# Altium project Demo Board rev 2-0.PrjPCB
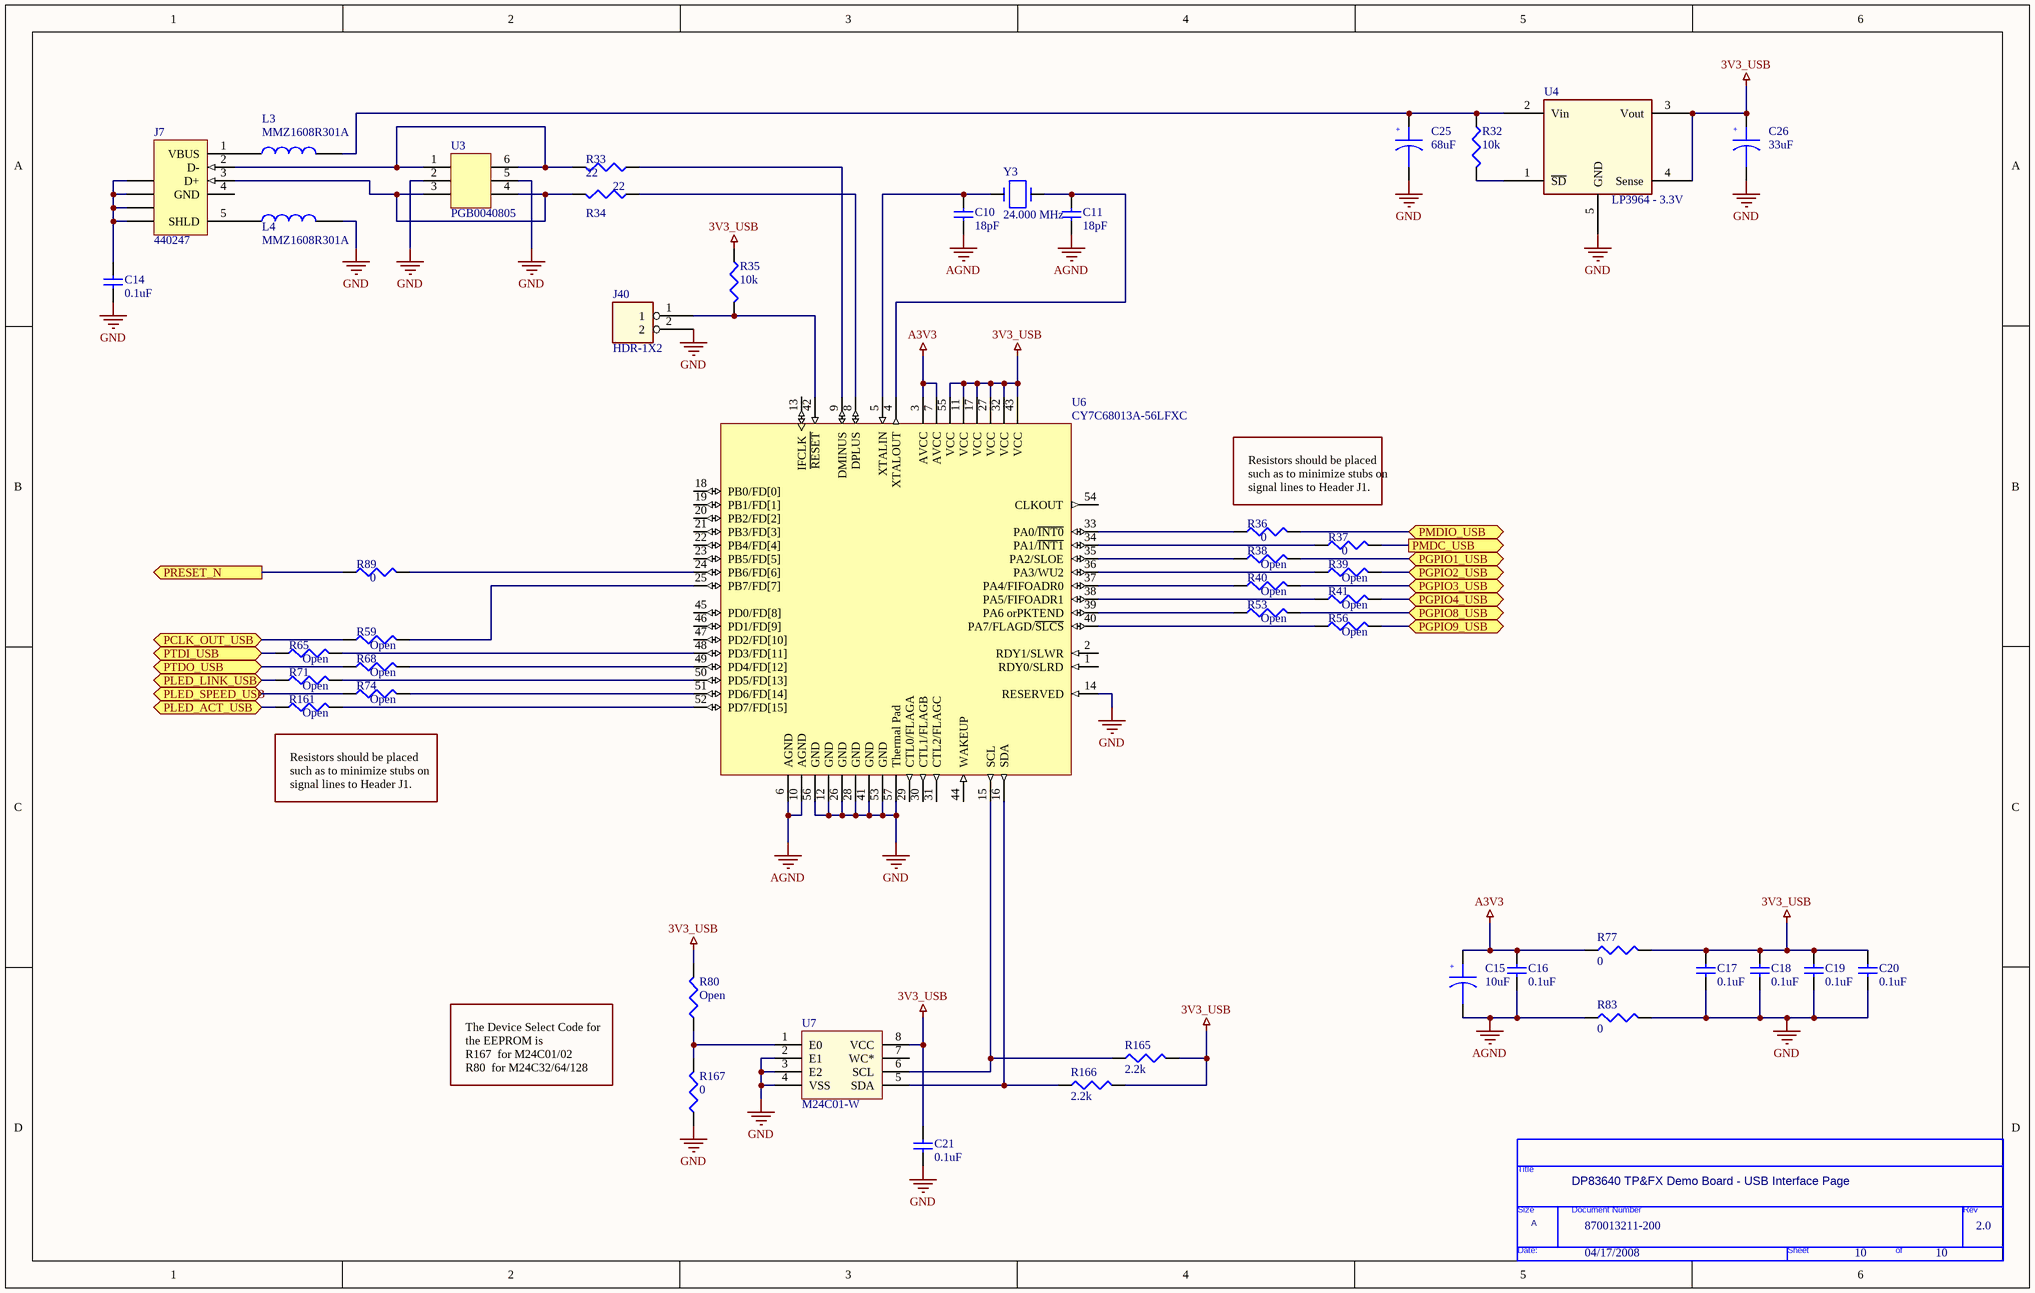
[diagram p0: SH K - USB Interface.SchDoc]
Project_date: 04/17/2008; Project_Drawing: 870013211-200; Project_revision: 2.0
10 sheets, 279 parts. Net scope: flat (ports and power ports of the same name join across sheets).
Sheets:
  SH K - USB Interface.SchDoc
  SH A - Cover.SchDoc
  SH B - HP.SchDoc
  SH C - POWER&CLOCK&MDIO.SchDoc
  SH E - STRAP OPTIONS.SchDoc
  SH F - GPIO.SchDoc
  SH G - TP Integrated Magnetics.SchDoc
  SH H - zFX.SchDoc
  SH I - MII.SchDoc
  SH J - ALP INTERFACE.SchDoc

## Sheet SH K - USB Interface.SchDoc
size B; SheetNumber: 10; SheetTotal: 10

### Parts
(Parts that share a designator on the sheet are numbered #1, #2 ... from top to bottom, then left to right.)
*#1  Title: DP83640 TP&FX Demo Board - USB Interface Page  Page Size: A  (hidden comment: TitleBlock0)  (graphical)
C10  18pF  [SMD0603-A-1]
C11  18pF  [SMD0603-A-1]
C14  0.1uF  [SMD0603-A-1]
C15  10uF  [SMD3528-B-1]
C16  0.1uF  [SMD0603-A-1]
C17  0.1uF  [SMD0603-A-1]
C18  0.1uF  [SMD0603-A-1]
C19  0.1uF  [SMD0603-A-1]
C20  0.1uF  [SMD0603-A-1]
C21  0.1uF  [SMD0603-A-1]
C25  68uF  [SMD3528-B-1]
C26  33uF  [SMD3528-B-1]
J7  440247  [440247]
J40  HDR-1X2  [CN-HDR1X2]
L3  MMZ1608R301A  [1608]
L4  MMZ1608R301A  [1608]
R32  10k  [SMD0603-A-1]
R33  22  [SMD0603-A-1]
R34  22  [SMD0603-A-1]
R35  10k  [SMD0603-A-1]
R36  0  [SMD0603-A-1]
R37  0  [SMD0603-A-1]
R38  Open  [SMD0603-A-1]
R39  Open  [SMD0603-A-1]
R40  Open  [SMD0603-A-1]
R41  Open  [SMD0603-A-1]
R53  Open  [SMD0603-A-1]
R56  Open  [SMD0603-A-1]
R59  Open  [SMD0603-A-1]
R65  Open  [SMD0603-A-1]
R68  Open  [SMD0603-A-1]
R71  Open  [SMD0603-A-1]
R74  Open  [SMD0603-A-1]
R77  0  [SMD0603-A-1]
R80  Open  [SMD0603-A-1]
R83  0  [SMD0603-A-1]
R89  0  [SMD0603-A-1]
R161  Open  [SMD0603-A-1]
R165  2.2k  [SMD0603-A-1]
R166  2.2k  [SMD0603-A-1]
R167  0  [SMD0603-A-1]
U3  PGB0040805  [PGB0040805]
U4  LP3964 - 3.3V  [SOT223-5]
U6  CY7C68013A-56LFXC  [LF56A_N]
U7  M24C01-W  [SO8 (MN)]
Y3  24.000 MHz  [HC49-US]

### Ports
PCLK_OUT_USB (bidir), PGPIO1_USB (bidir), PGPIO2_USB (bidir), PGPIO3_USB (bidir), PGPIO4_USB (bidir), PGPIO8_USB (bidir), PGPIO9_USB (bidir), PLED_ACT_USB (bidir), PLED_LINK_USB (bidir), PLED_SPEED_USB (bidir), PMDC_USB (out), PMDIO_USB (bidir), PRESET_N (out), PTDI_USB (bidir), PTDO_USB (bidir)

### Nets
3V3_USB: C17.1 C18.1 C19.1 C20.1 C21.1 C26.1 R35.1 R77.2 R80.2 R165.2 R166.2 U4.3(Vout) U4.4(Sense) U6.11(VCC) U6.17(VCC) U6.27(VCC) U6.32(VCC) U6.43(VCC) U6.55(VCC) U7.8(VCC)
A3V3: C15.1 C16.1 R77.1 U6.3(AVCC) U6.7(AVCC)
AGND: C10.2 C11.2 C15.2 C16.2 R83.1 U6.6(AGND) U6.10(AGND)
GND: C14.2 C17.2 C18.2 C19.2 C20.2 C21.2 C25.2 C26.2 J40.2 L4.2 R83.2 R167.1 U3.2 U3.5 U4.5(GND) U6.12(GND) U6.14(RESERVED) U6.26(GND) U6.28(GND) U6.41(GND) U6.53(GND) U6.56(GND) U6.57(Thermal_Pad) U7.2(E1) U7.3(E2) U7.4(VSS)
TDI: R65.1 ; port PTDI_USB
TDO: R68.1 ; port PTDO_USB
NetC10_1: C10.1 U6.5(XTALIN) Y3.2
NetC11_1: C11.1 U6.4(XTALOUT) Y3.1
NetC14_1: C14.1 J7.6(SHLD) J7.7(SHLD) J7.8(SHLD) J7.9(SHLD)
NetC25_1: C25.1 L3.2 R32.1 U4.2(Vin)
NetJ1_1: R38.2 ; port PGPIO1_USB
NetJ1_3: R39.2 ; port PGPIO2_USB
NetJ1_5: R40.2 ; port PGPIO3_USB
NetJ1_7: R41.2 ; port PGPIO4_USB
NetJ1_9: R161.1 ; port PLED_ACT_USB
NetJ1_11: R74.1 ; port PLED_SPEED_USB
NetJ1_13: R71.1 ; port PLED_LINK_USB
NetJ1_15: R53.2 ; port PGPIO8_USB
NetJ1_17: R56.2 ; port PGPIO9_USB
NetJ1_23: R59.1 ; port PCLK_OUT_USB
NetJ3_3: R37.2 ; port PMDC_USB
NetJ4_3: R36.2 ; port PMDIO_USB
NetJ7_1: J7.1(VBUS) L3.1
NetJ7_2: J7.2(D-) R33.2 U3.1 U3.6
NetJ7_3: J7.3(D+) R34.2 U3.3 U3.4
NetJ7_5: J7.5(SHLD) L4.1
NetJ8_1: R89.1 ; port PRESET_N
NetJ40_1: J40.1 R35.2 U6.42(~{RESET})
NetR32_2: R32.2 U4.1(~{SD})
NetR33_1: R33.1 U6.9(DMINUS)
NetR34_1: R34.1 U6.8(DPLUS)
NetR36_1: R36.1 U6.33(PA0/~{INT0})
NetR37_1: R37.1 U6.34(PA1/~{INT1})
NetR38_1: R38.1 U6.35(PA2/SLOE)
NetR39_1: R39.1 U6.36(PA3/WU2)
NetR40_1: R40.1 U6.37(PA4/FIFOADR0)
NetR41_1: R41.1 U6.38(PA5/FIFOADR1)
NetR53_1: R53.1 U6.39(PA6_orPKTEND)
NetR56_1: R56.1 U6.40(PA7/FLAGD/~{SLCS})
NetR59_2: R59.2 U6.25(PB7/FD[7])
NetR65_2: R65.2 U6.48(PD3/FD[11])
NetR68_2: R68.2 U6.49(PD4/FD[12])
NetR71_2: R71.2 U6.50(PD5/FD[13])
NetR74_2: R74.2 U6.51(PD6/FD[14])
NetR80_1: R80.1 R167.2 U7.1(E0)
NetR89_2: R89.2 U6.24(PB6/FD[6])
NetR161_2: R161.2 U6.52(PD7/FD[15])
NetR165_1: R165.1 U6.15(SCL) U7.6(SCL)
NetR166_1: R166.1 U6.16(SDA) U7.5(SDA)

Not connected (* = marked no-connect by the designer): J7 4(GND); U6 1(RDY0/SLRD) 2(RDY1/SLWR) 13(IFCLK) 18(PB0/FD[0]) 19(PB1/FD[1]) 20(PB2/FD[2]) 21(PB3/FD[3]) 22(PB4/FD[4]) 23(PB5/FD[5]) 29(CTL0/FLAGA) 30(CTL1/FLAGB) 31(CTL2/FLAGC) 44(WAKEUP) 45(PD0/FD[8]) 46(PD1/FD[9]) 47(PD2/FD[10]) 54(CLKOUT); U7 7(WC*)

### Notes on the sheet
- Resistors should be placed such as to minimize stubs on signal lines to Header J1.
- The Device Select Code for the EEPROM is
  R167  for M24C01/02
  R80  for M24C32/64/128

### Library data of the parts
*#1 = TitleBlock0: Page Number: 1
C10 C11 C14 C16-C21 = C-0_0.1uF
C25 C26 = 10uF
J7 = 440247-1: USB 2.0, Right Angle, SMT, B Type, Receptacle, 5 Position, Black; ContactMaterial: Copper Alloy; ContactPlating: Gold (30); PCB_Layout: Complies with manufacturer's recommendation.; DrillSize: Corresponds to nominal value.; PanelGround: Without
L3 L4 = MMZ1608: Manufacturer: TDK; Description: Chip Bead (SMD) Series MMZ1608
R32-R41 R53 R56 R59 R65 R68 R71 R74 R77 R80 R83 R89 R161 R165-R167 = R
U3 = PGB0040805: Manufacturer: Littelfuse; Description: PGB Series 0805 Surface Mount ESD Suppressor
U4 = LM3964-3.3V
U6 = CY7C68013A-56LFXC: EZ-USB FX2LP USB Microcontroller Ideal for Non-Battery Powered Applications,16K RAM, 24 I/Os, 56-Pin QFN, Pb-Free, Commercial Grade
Y3 = CRYSTAL

## Sheet SH A - Cover.SchDoc
size 386 x 246 mm; Revision: 1.1; SheetNumber: 1; SheetTotal: 10
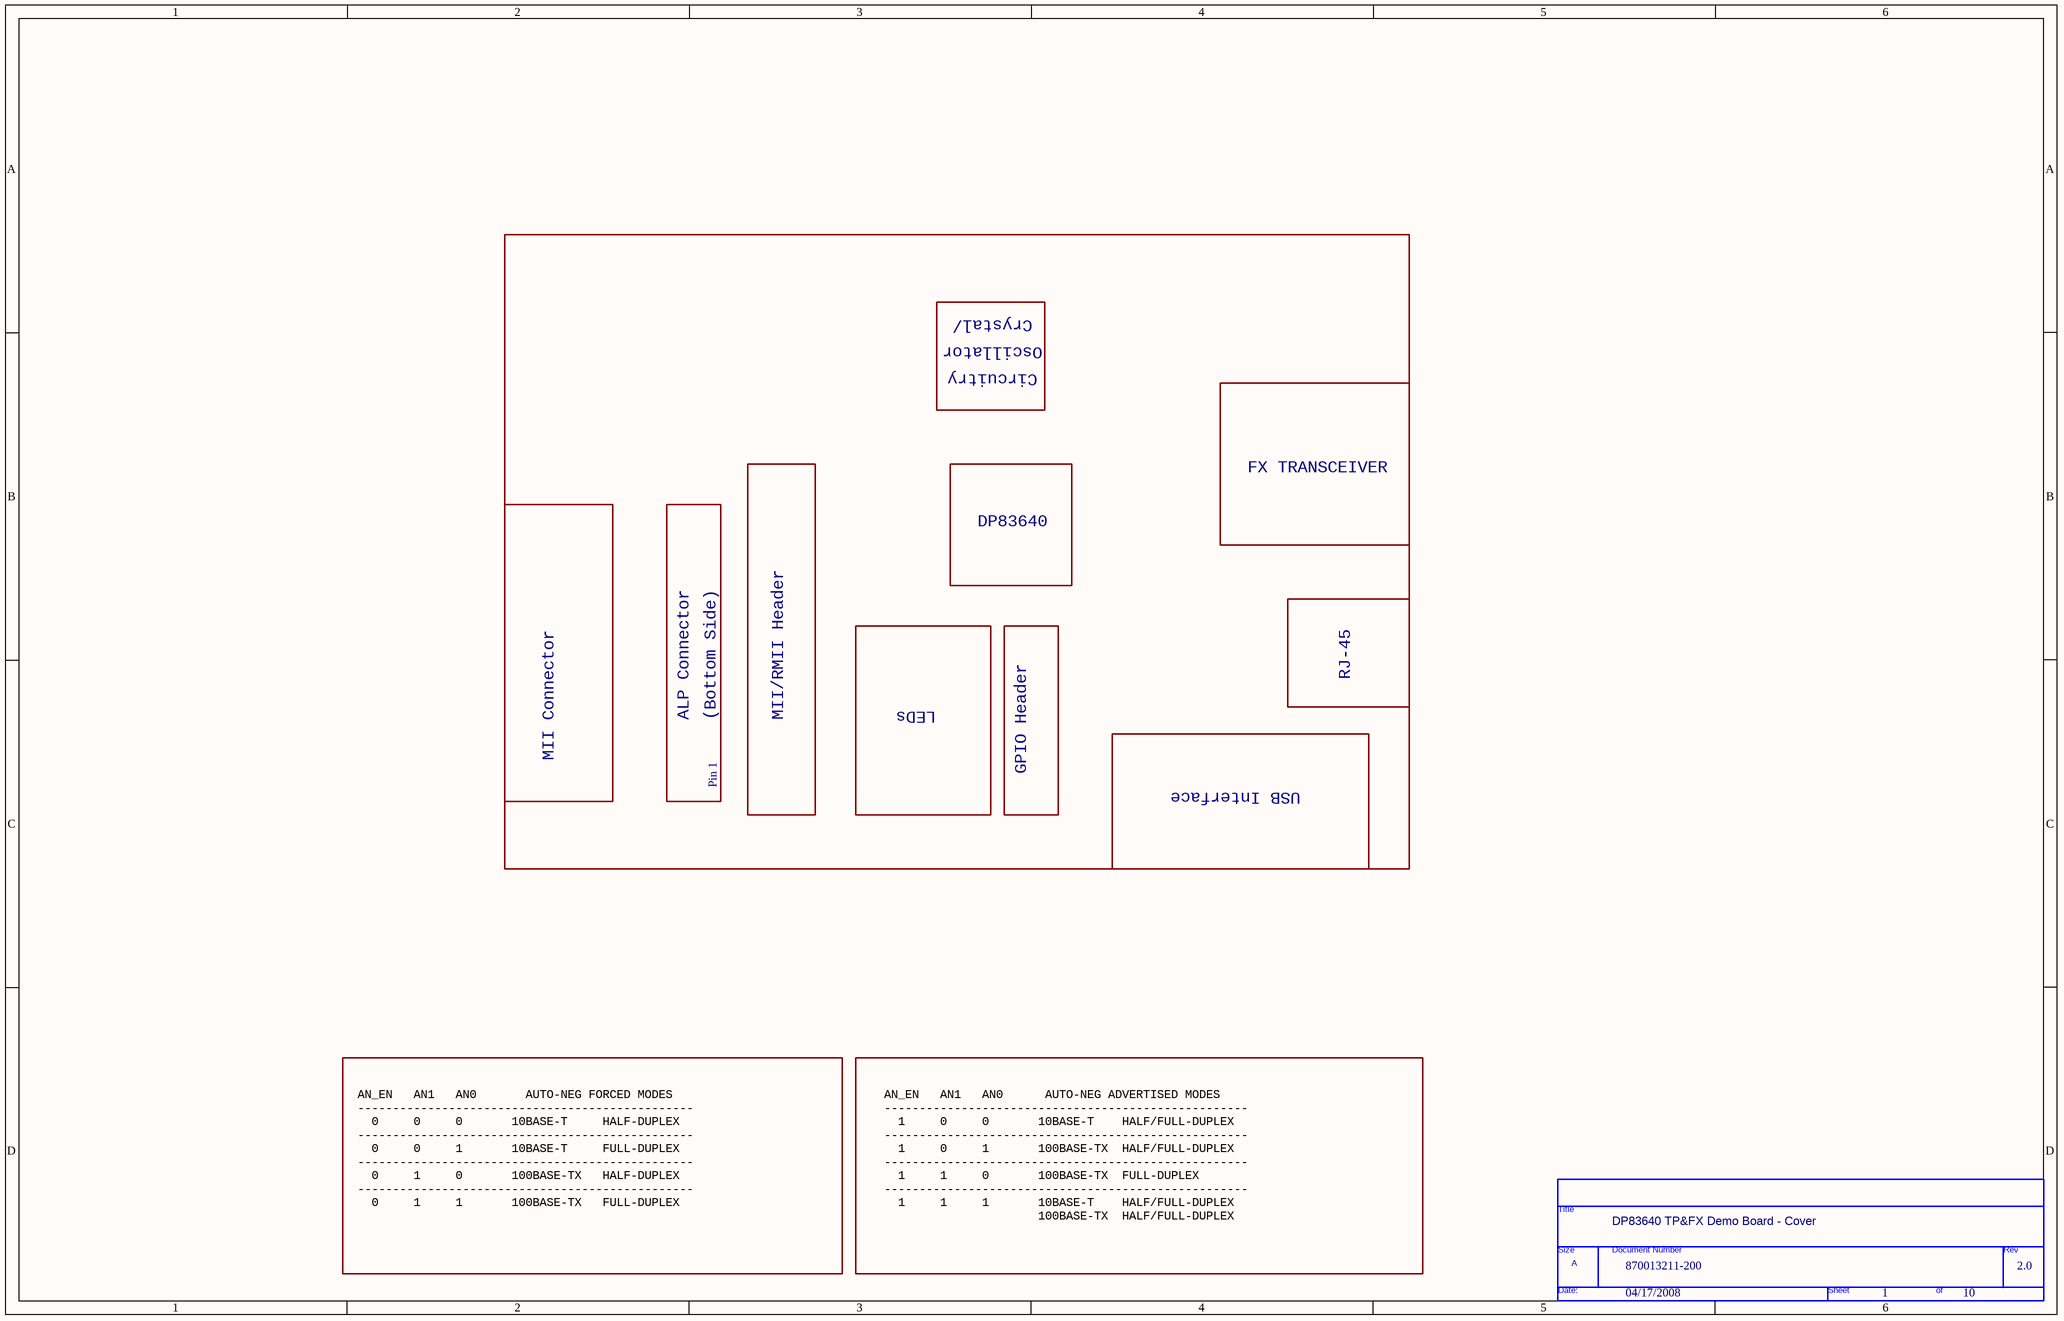
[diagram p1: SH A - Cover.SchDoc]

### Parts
(Parts that share a designator on the sheet are numbered #1, #2 ... from top to bottom, then left to right.)
*#2  Title: DP83640 TP&FX Demo Board - Cover  Page Size: A  (hidden comment: TitleBlock0)  (graphical)

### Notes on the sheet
- Crystal/
- Circuitry
- Oscillator
- DP83640
- FX TRANSCEIVER
- ALP Connector
- (Bottom Side)
- MII/RMII Header
- LEDs
- RJ-45
- MII Connector
- Pin 1
- GPIO Header
- USB Interface
- AN_EN   AN1   AN0       AUTO-NEG FORCED MODES
  ------------------------------------------------
  0     0     0       10BASE-T     HALF-DUPLEX
  ------------------------------------------------
  0     0     1       10BASE-T     FULL-DUPLEX
  ------------------------------------------------
  0     1     0       100BASE-TX   HALF-DUPLEX
  ------------------------------------------------
  0     1     1       100BASE-TX   FULL-DUPLEX
- AN_EN   AN1   AN0      AUTO-NEG ADVERTISED MODES
  ----------------------------------------------------
  1     0     0       10BASE-T    HALF/FULL-DUPLEX
  ----------------------------------------------------
  1     0     1       100BASE-TX  HALF/FULL-DUPLEX
  ----------------------------------------------------
  1     1     0       100BASE-TX  FULL-DUPLEX
  ----------------------------------------------------
  1     1     1       10BASE-T    HALF/FULL-DUPLEX
  100BASE-TX  HALF/FULL-DUPLEX

## Sheet SH B - HP.SchDoc
size 386 x 246 mm; Revision: 1.1; SheetNumber: 2; SheetTotal: 10
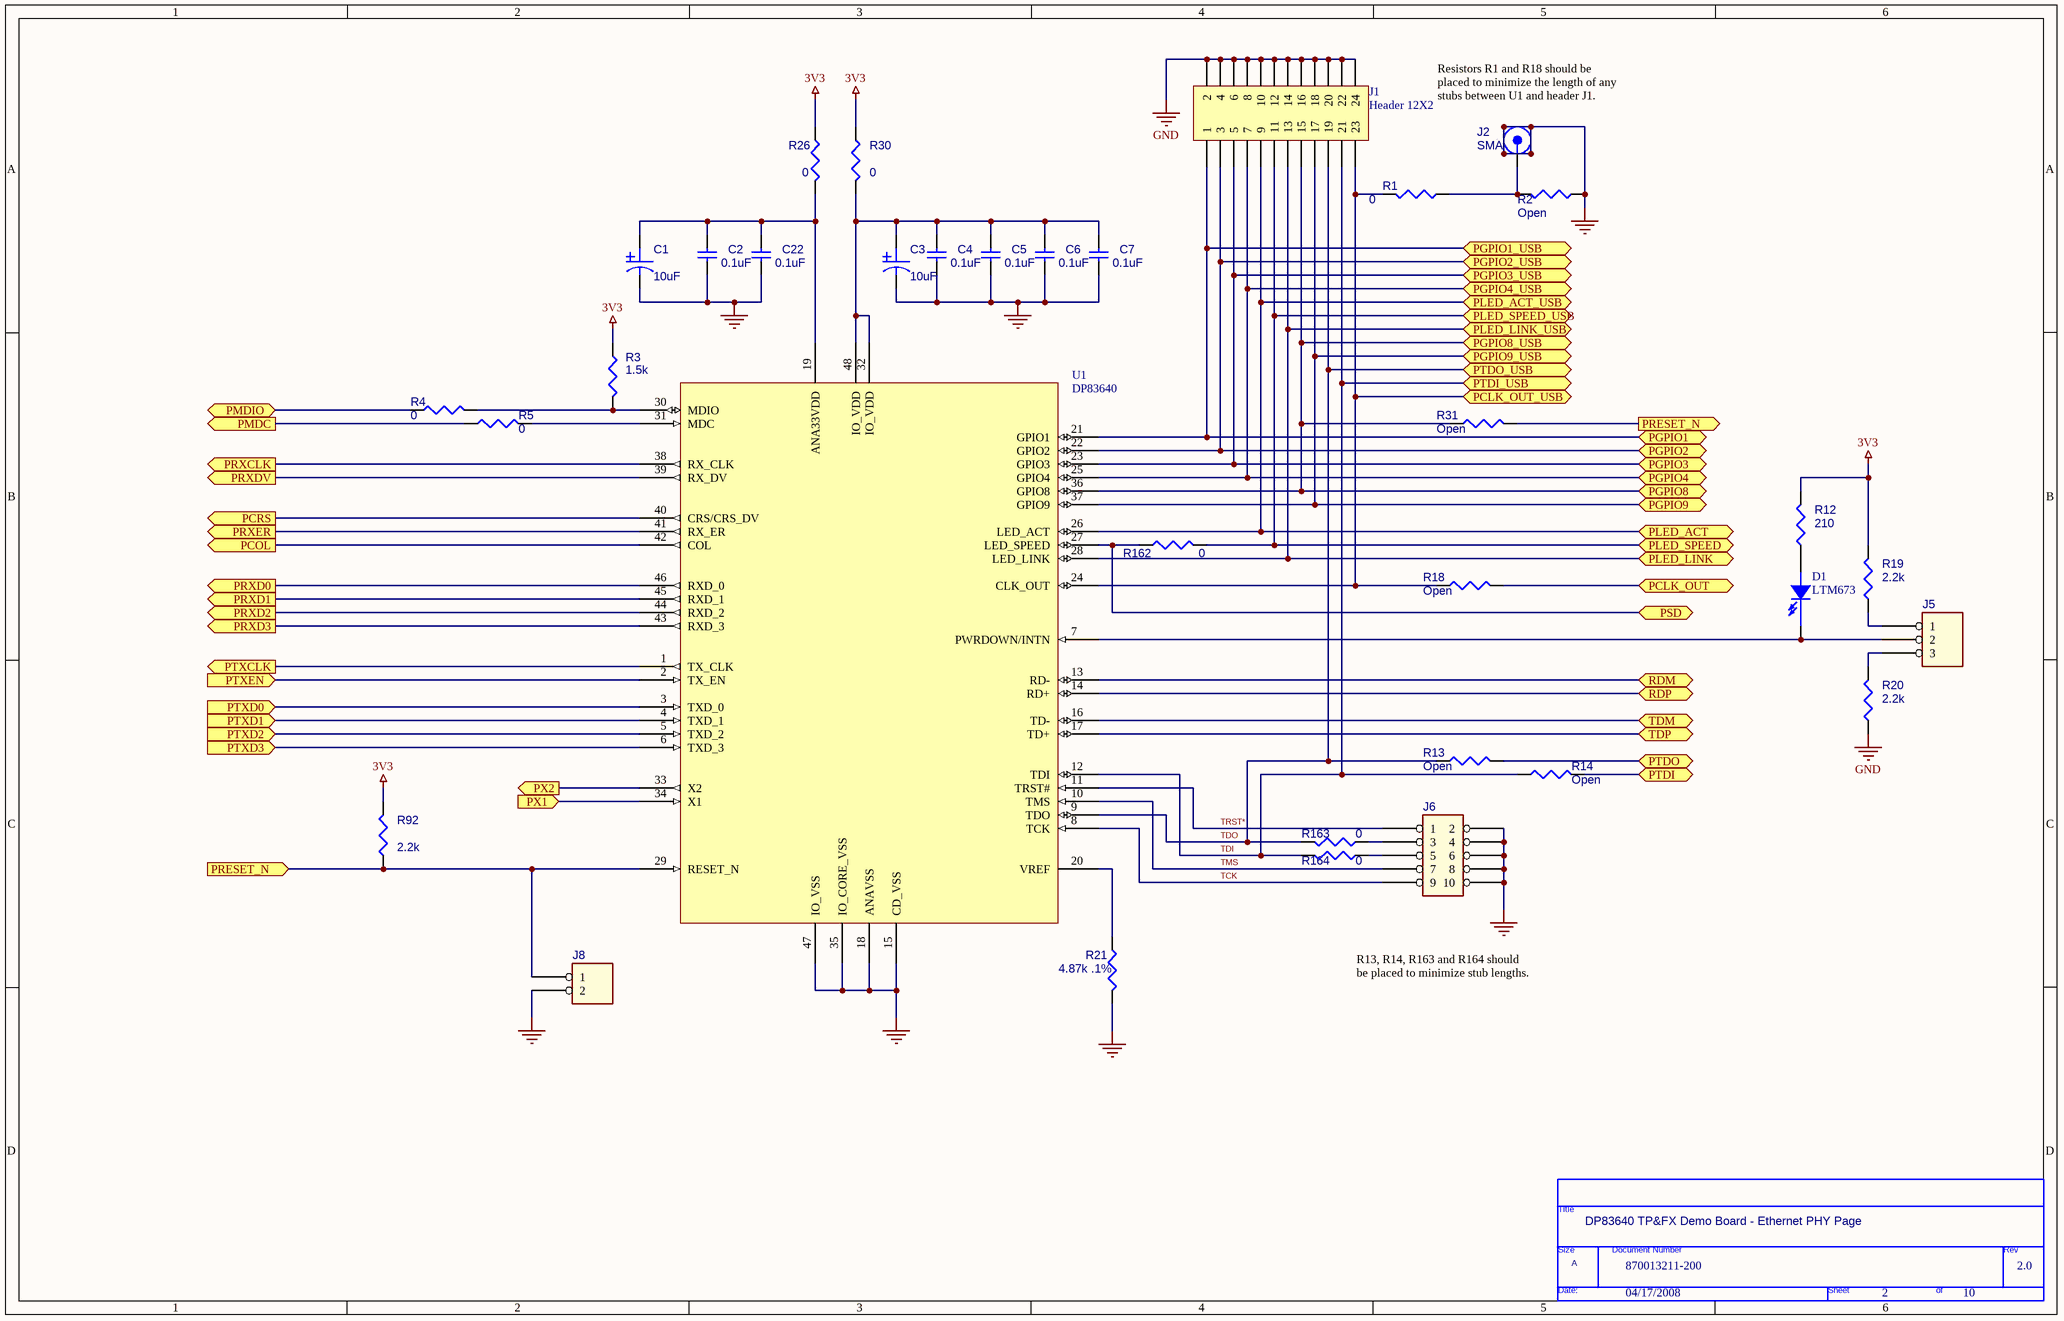
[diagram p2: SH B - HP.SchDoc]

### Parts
(Parts that share a designator on the sheet are numbered #1, #2 ... from top to bottom, then left to right.)
*#3  Title: DP83640 TP&FX Demo Board - Ethernet PHY Page  Page Size: A  (hidden comment: TitleBlock0)  (graphical)
C1  10uF  [7343]
C2  0.1uF  [SMD0603-A-1]
C3  10uF  [7343]
C4  0.1uF  [SMD0603-A-1]
C5  0.1uF  [SMD0603-A-1]
C6  0.1uF  [SMD0603-A-1]
C7  0.1uF  [SMD0603-A-1]
C22  0.1uF  [SMD0603-A-1]
D1  LTM673  [OSRAM LTM673]
J1  Header 12X2  [HDR2X12]
J2  SMA  [J608-ND]
J5  HDR_1X3  [CN-HDR1X3]  (value not drawn)
J6  CON2x5_TH  [cn-hdr2x5]  (value not drawn)
J8  HDR-1X2  [CN-HDR1X2]  (value not drawn)
R1  0  [SMD0603-A-1]
R2  Open  [SMD0603-A-1]
R3  1.5k  [SMD0603-A-1]
R4  0  [SMD0603-A-1]
R5  0  [SMD0603-A-1]
R12  210  [SMD0603-A-1]
R13  Open  [SMD0603-A-1]
R14  Open  [SMD0603-A-1]
R18  Open  [SMD0603-A-1]
R19  2.2k  [SMD0603-A-1]
R20  2.2k  [SMD0603-A-1]
R21  4.87k .1%  [SMD0603-A-1]
R26  0  [SMD0603-A-1]
R30  0  [SMD0603-A-1]
R31  Open  [SMD0603-A-1]
R92  2.2k  [SMD0603-A-1]
R162  0  [SMD0603-A-1]
R163  0  [SMD0603-A-1]
R164  0  [SMD0603-A-1]
U1  DP83640  [VBH48A]

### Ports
PCLK_OUT (bidir), PCLK_OUT_USB (bidir), PCOL (out), PCRS (out), PGPIO1 (bidir), PGPIO1_USB (bidir), PGPIO2 (bidir), PGPIO2_USB (bidir), PGPIO3 (bidir), PGPIO3_USB (bidir), PGPIO4 (bidir), PGPIO4_USB (bidir), PGPIO8 (bidir), PGPIO8_USB (bidir), PGPIO9 (bidir), PGPIO9_USB (bidir), PLED_ACT (bidir), PLED_ACT_USB (bidir), PLED_LINK (bidir), PLED_LINK_USB (bidir), PLED_SPEED (bidir), PLED_SPEED_USB (bidir), PMDC (out), PMDIO (bidir), PRESET_N (in), PRESET_N (out), PRXCLK (out), PRXD0 (out), PRXD1 (out), PRXD2 (out), PRXD3 (out), PRXDV (out), PRXER (out), PSD (bidir), PTDI (bidir), PTDI_USB (bidir), PTDO (bidir), PTDO_USB (bidir), PTXCLK (out), PTXD0 (in), PTXD1 (in), PTXD2 (in), PTXD3 (in), PTXEN (in), PX1 (in), PX2 (out), RDM (bidir), RDP (bidir), TDM (bidir), TDP (bidir)

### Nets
3V3: R3.1 R12.2 R19.2 R26.2 R30.2 R92.2
GND: C1.2 C2.2 C3.2 C4.2 C5.2 C6.2 C7.2 C22.2 J1.2 J1.4 J1.6 J1.8 J1.10 J1.12 J1.14 J1.16 J1.18 J1.20 J1.22 J1.24 J2.2(GND2) J2.3(GND3) J2.4(GND4) J2.5(GND5) J6.2 J6.4 J6.6 J6.8 J6.10 J8.2 R2.2 R20.1 R21.2 U1.15(CD_VSS) U1.18(ANAVSS) U1.35(IO_CORE_VSS) U1.47(IO_VSS)
PCOL: U1.42(COL) ; port PCOL
PCRS: U1.40(CRS/CRS_DV) ; port PCRS
PRXCLK: U1.38(RX_CLK) ; port PRXCLK
PRXD0: U1.46(RXD_0) ; port PRXD0
PRXD1: U1.45(RXD_1) ; port PRXD1
PRXD2: U1.44(RXD_2) ; port PRXD2
PRXD3: U1.43(RXD_3) ; port PRXD3
PRXDV: U1.39(RX_DV) ; port PRXDV
PRXER: U1.41(RX_ER) ; port PRXER
PTXCLK: U1.1(TX_CLK) ; port PTXCLK
PTXD0: U1.3(TXD_0) ; port PTXD0
PTXD1: U1.4(TXD_1) ; port PTXD1
PTXD2: U1.5(TXD_2) ; port PTXD2
PTXD3: U1.6(TXD_3) ; port PTXD3
PTXEN: U1.2(TX_EN) ; port PTXEN
TCK: J6.9 U1.8(TCK)
TDI: J1.21 R14.1 R164.1 U1.12(TDI) ; port PTDI_USB
TDO: J1.19 R13.1 R163.1 U1.9(TDO) ; port PTDO_USB
TMS: J6.7 U1.10(TMS)
TRST*: J6.1 U1.11(TRST#)
NetC1_1: C1.1 C2.1 C22.1 R26.1 U1.19(ANA33VDD)
NetC3_1: C3.1 C4.1 C5.1 C6.1 C7.1 R30.1 U1.32(IO_VDD) U1.48(IO_VDD)
NetD1_1: D1.1(Cathode) J5.2 U1.7(PWRDOWN/INTN)
NetD1_2: D1.2(Anode) R12.1
NetJ1_1: J1.1 U1.21(GPIO1) ; port PGPIO1, port PGPIO1_USB
NetJ1_3: J1.3 U1.22(GPIO2) ; port PGPIO2, port PGPIO2_USB
NetJ1_5: J1.5 U1.23(GPIO3) ; port PGPIO3, port PGPIO3_USB
NetJ1_7: J1.7 U1.25(GPIO4) ; port PGPIO4, port PGPIO4_USB
NetJ1_9: J1.9 U1.26(LED_ACT) ; port PLED_ACT, port PLED_ACT_USB
NetJ1_11: J1.11 R162.2 ; port PLED_SPEED, port PLED_SPEED_USB
NetJ1_13: J1.13 U1.28(LED_LINK) ; port PLED_LINK, port PLED_LINK_USB
NetJ1_15: J1.15 R31.1 U1.36(GPIO8) ; port PGPIO8, port PGPIO8_USB
NetJ1_17: J1.17 U1.37(GPIO9) ; port PGPIO9, port PGPIO9_USB
NetJ1_23: J1.23 R1.1 R18.1 U1.24(CLK_OUT) ; port PCLK_OUT_USB
NetJ2_1: J2.1 R1.2 R2.1
NetJ3_2: R5.1 ; port PMDC
NetJ4_2: R4.1 ; port PMDIO
NetJ5_1: J5.1 R19.1
NetJ5_3: J5.3 R20.2
NetJ6_3: J6.3 R163.2
NetJ6_5: J6.5 R164.2
NetJ8_1: J8.1 R31.2 R92.1 U1.29(RESET_N) ; port PRESET_N
NetJ60_23: R18.2 ; port PCLK_OUT
NetJ60_24: R13.2 ; port PTDO
NetJ60_26: R14.2 ; port PTDI
NetR3_2: R3.2 R4.2 U1.30(MDIO)
NetR5_2: R5.2 U1.31(MDC)
NetR21_1: R21.1 U1.20(VREF)
NetR22_1: U1.33(X2) ; port PX2
NetR25_1: U1.34(X1) ; port PX1
NetR112_1: U1.17(TD+) ; port TDP
NetR114_2: U1.16(TD-) ; port TDM
NetR116_2: U1.13(RD-) ; port RDM
NetR118_2: U1.14(RD+) ; port RDP
NetR128_1: R162.1 U1.27(LED_SPEED) ; port PSD

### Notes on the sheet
- (near J2) Resistors R1 and R18 should be placed to minimize the length of any stubs between U1 and header J1.
- R13, R14, R163 and R164 should be placed to minimize stub lengths.

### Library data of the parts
C1 C3 = CAP_POL_0
C2 C4-C7 C22 = C-0_0.1uF: Part Description: CAP, SMD, Ceramic, 0603; Voltage: 50V; Tolerance: +80-20%
D1 = LED LTM673_1
J1 = Header 12X2: Header, 12-Pin, Dual row
J2 = SMA_1
J5 = HDR_1X3_Dup1
J6 = CON2x5_TH_0
J8 = HDR-1X2_Dup1
R1 R2 R26 R30 R163 R164 = R: Part Description: RES, SMD, 0603; Power: 1/16W; Tolerance: 1%
R3 R162 = R: Part Description: RES, SMD, 0805; Tolerance: 1%; Power: 1/10W
R4 R5 R12-R14 R18-R20 R31 R92 = R: Part Description: RES, SMD, 0603; Tolerance: 5%; Power: 1/16W
R21 = R: Part Description: RES, SMD, 0603; Power: 1/16W
U1 = DP83640T_0

## Sheet SH C - POWER&CLOCK&MDIO.SchDoc
size 386 x 246 mm; SheetNumber: 3; SheetTotal: 10
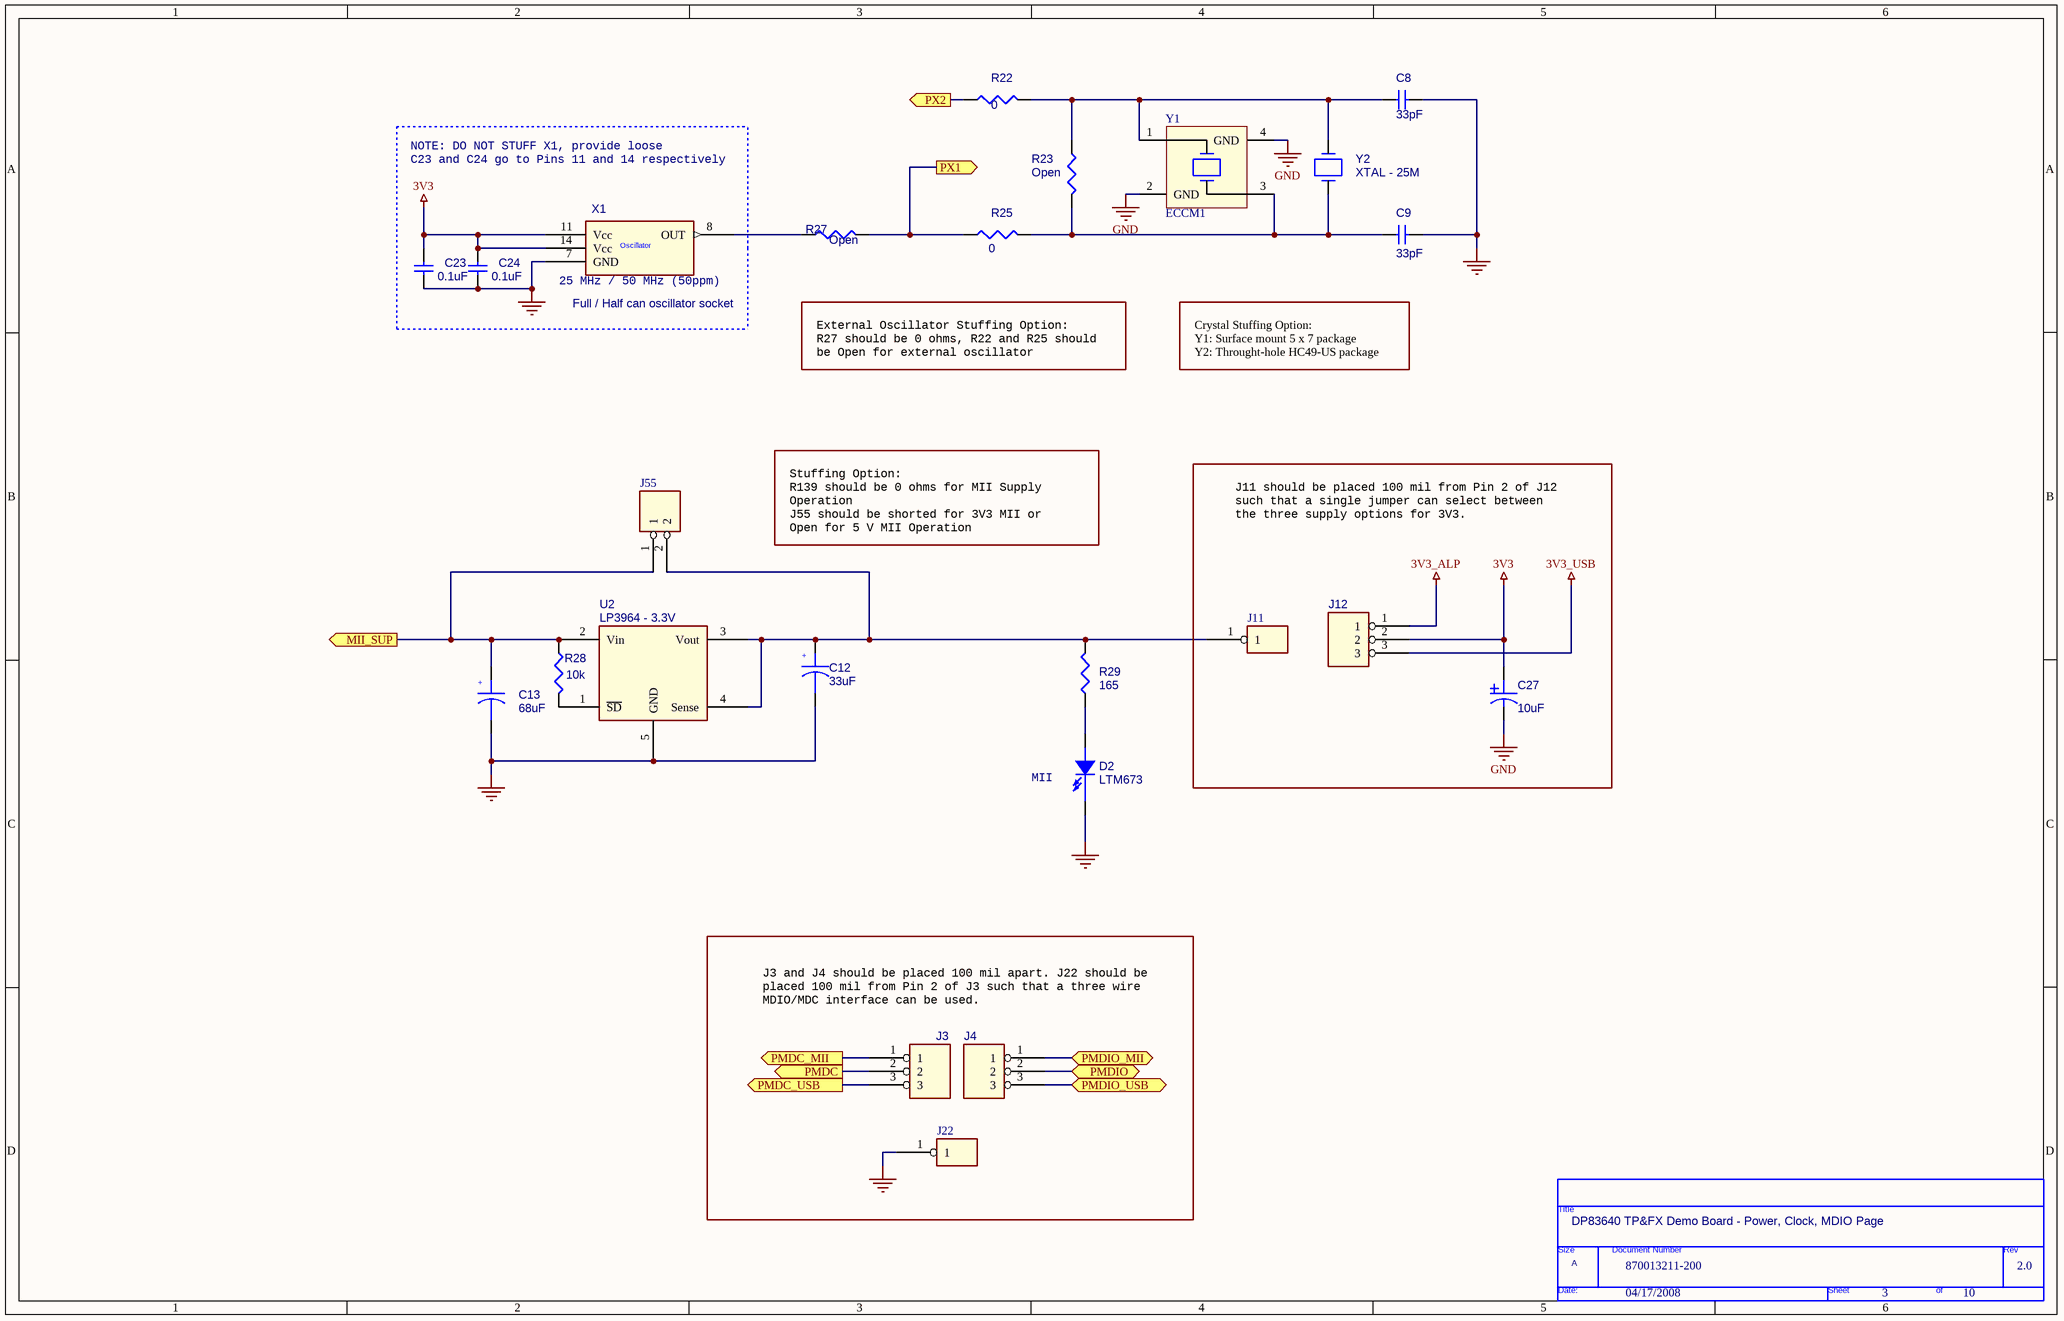
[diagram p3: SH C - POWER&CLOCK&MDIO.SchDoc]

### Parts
(Parts that share a designator on the sheet are numbered #1, #2 ... from top to bottom, then left to right.)
*#4  Title: DP83640 TP&FX Demo Board - Power, Clock, MDIO Page  Page Size: A  (hidden comment: TitleBlock0)  (graphical)
C8  33pF  [SMD0603-A-1]
C9  33pF  [SMD0603-A-1]
C12  33uF  [SMD3528-B-1]
C13  68uF  [SMD3528-B-1]
C23  0.1uF  [SMD0603-A-1]
C24  0.1uF  [SMD0603-A-1]
C27  10uF  [7343]
D2  LTM673  [OSRAM LTM673]
J3  HDR_1X3  [CN-HDR1X3]  (value not drawn)
J4  HDR_1X3  [CN-HDR1X3]  (value not drawn)
J11  HDR-1X1  [CN-HDR1X1]  (value not drawn)
J12  HDR_1X3  [CN-HDR1X3]  (value not drawn)
J22  HDR-1X1  [CN-HDR1X1]  (value not drawn)
J55  HDR-1X2  [CN-HDR1X2]  (value not drawn)
R22  0  [SMD0603-A-1]
R23  Open  [SMD0603-A-1]
R25  0  [SMD0603-A-1]
R27  Open  [SMD0603-A-1]
R28  10k  [SMD0603-A-1]
R29  165  [SMD0603-A-1]
U2  LP3964 - 3.3V  [SOT223-5]
X1  Full / Half can oscillator socket  [OSC14-4P]
Y1  ECCM1  [ECCM1]
Y2  XTAL - 25M  [HC49-US]

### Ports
MII_SUP (out), PMDC (out), PMDC_MII (out), PMDC_USB (out), PMDIO (bidir), PMDIO_MII (bidir), PMDIO_USB (bidir), PX1 (out), PX2 (out)

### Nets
3V3: C23.1 C24.1 C27.1 J12.2 X1.11(Vcc) X1.14(Vcc)
3V3_ALP: J12.1
3V3_USB: J12.3
GND: C8.2 C9.2 C12.2 C13.2 C23.2 C24.2 C27.2 D2.1(Cathode) J22.1 U2.5(GND) X1.7(GND) Y1.2(GND) Y1.4(GND)
PMDC: J3.1 ; port PMDC_MII
PMDIO: J4.1 ; port PMDIO_MII
NetC8_1: C8.1 R22.2 R23.1 Y1.1 Y2.2
NetC9_1: C9.1 R23.2 R25.2 Y1.3 Y2.1
NetC12_1: C12.1 J11.1 J55.2 R29.2 U2.3(Vout) U2.4(Sense)
NetC13_1: C13.1 J55.1 R28.1 U2.2(Vin) ; port MII_SUP
NetD2_2: D2.2(Anode) R29.1
NetJ3_2: J3.2 ; port PMDC
NetJ3_3: J3.3 ; port PMDC_USB
NetJ4_2: J4.2 ; port PMDIO
NetJ4_3: J4.3 ; port PMDIO_USB
NetR22_1: R22.1 ; port PX2
NetR25_1: R25.1 R27.2 ; port PX1
NetR27_1: R27.1 X1.8(OUT)
NetR28_2: R28.2 U2.1(~{SD})

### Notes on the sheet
- NOTE: DO NOT STUFF X1, provide loose
- C23 and C24 go to Pins 11 and 14 respectively
- (near X1) 25 MHz / 50 MHz (50ppm)
- External Oscillator Stuffing Option:
  R27 should be 0 ohms, R22 and R25 should be Open for external oscillator
- Crystal Stuffing Option:
  Y1: Surface mount 5 x 7 package
  Y2: Throught-hole HC49-US package
- Stuffing Option:
  R139 should be 0 ohms for MII Supply Operation
  J55 should be shorted for 3V3 MII or
  Open for 5 V MII Operation
- J11 should be placed 100 mil from Pin 2 of J12
  such that a single jumper can select between
  the three supply options for 3V3.
- (near D2) MII
- J3 and J4 should be placed 100 mil apart. J22 should be placed 100 mil from Pin 2 of J3 such that a three wire MDIO/MDC interface can be used.

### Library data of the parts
C8 C9 = SMALL CAP: Part Description: CAP, SMD, Ceramic, 0805; Tolerance: 10%; Voltage: 50V
C12 C13 = 10uF
C23 C24 = C-0_0.1uF: as C2 on sheet SH B - HP
C27 = CAP_POL_0
D2 = LED LTM673_1: Manufacturer: OSRAM/LTM673-R1S2-35; Part Description: Hyper-Bright LED
R22 R25 = R: as R4 on sheet SH B - HP
R23 = R: Part Description: RES, SMD, 0603; Power: 1/16W; Tolerance: 5%
R27-R29 = R: as R1 on sheet SH B - HP
U2 = LM3964-3.3V: Manufacturer: NSC/LP3964EMP-3.3; Part Description: Voltage Regulator 5V-3.3V
X1 = OSC-25_2: Part Description: 25 MHz/50 MHz Oscillator (50 ppm), 3.3V
Y1 = Crystal - ECCM1
Y2 = CRYSTAL: Part Description: Crystal, 25.000M

## Sheet SH E - STRAP OPTIONS.SchDoc
size 386 x 246 mm; SheetNumber: 4; SheetTotal: 10
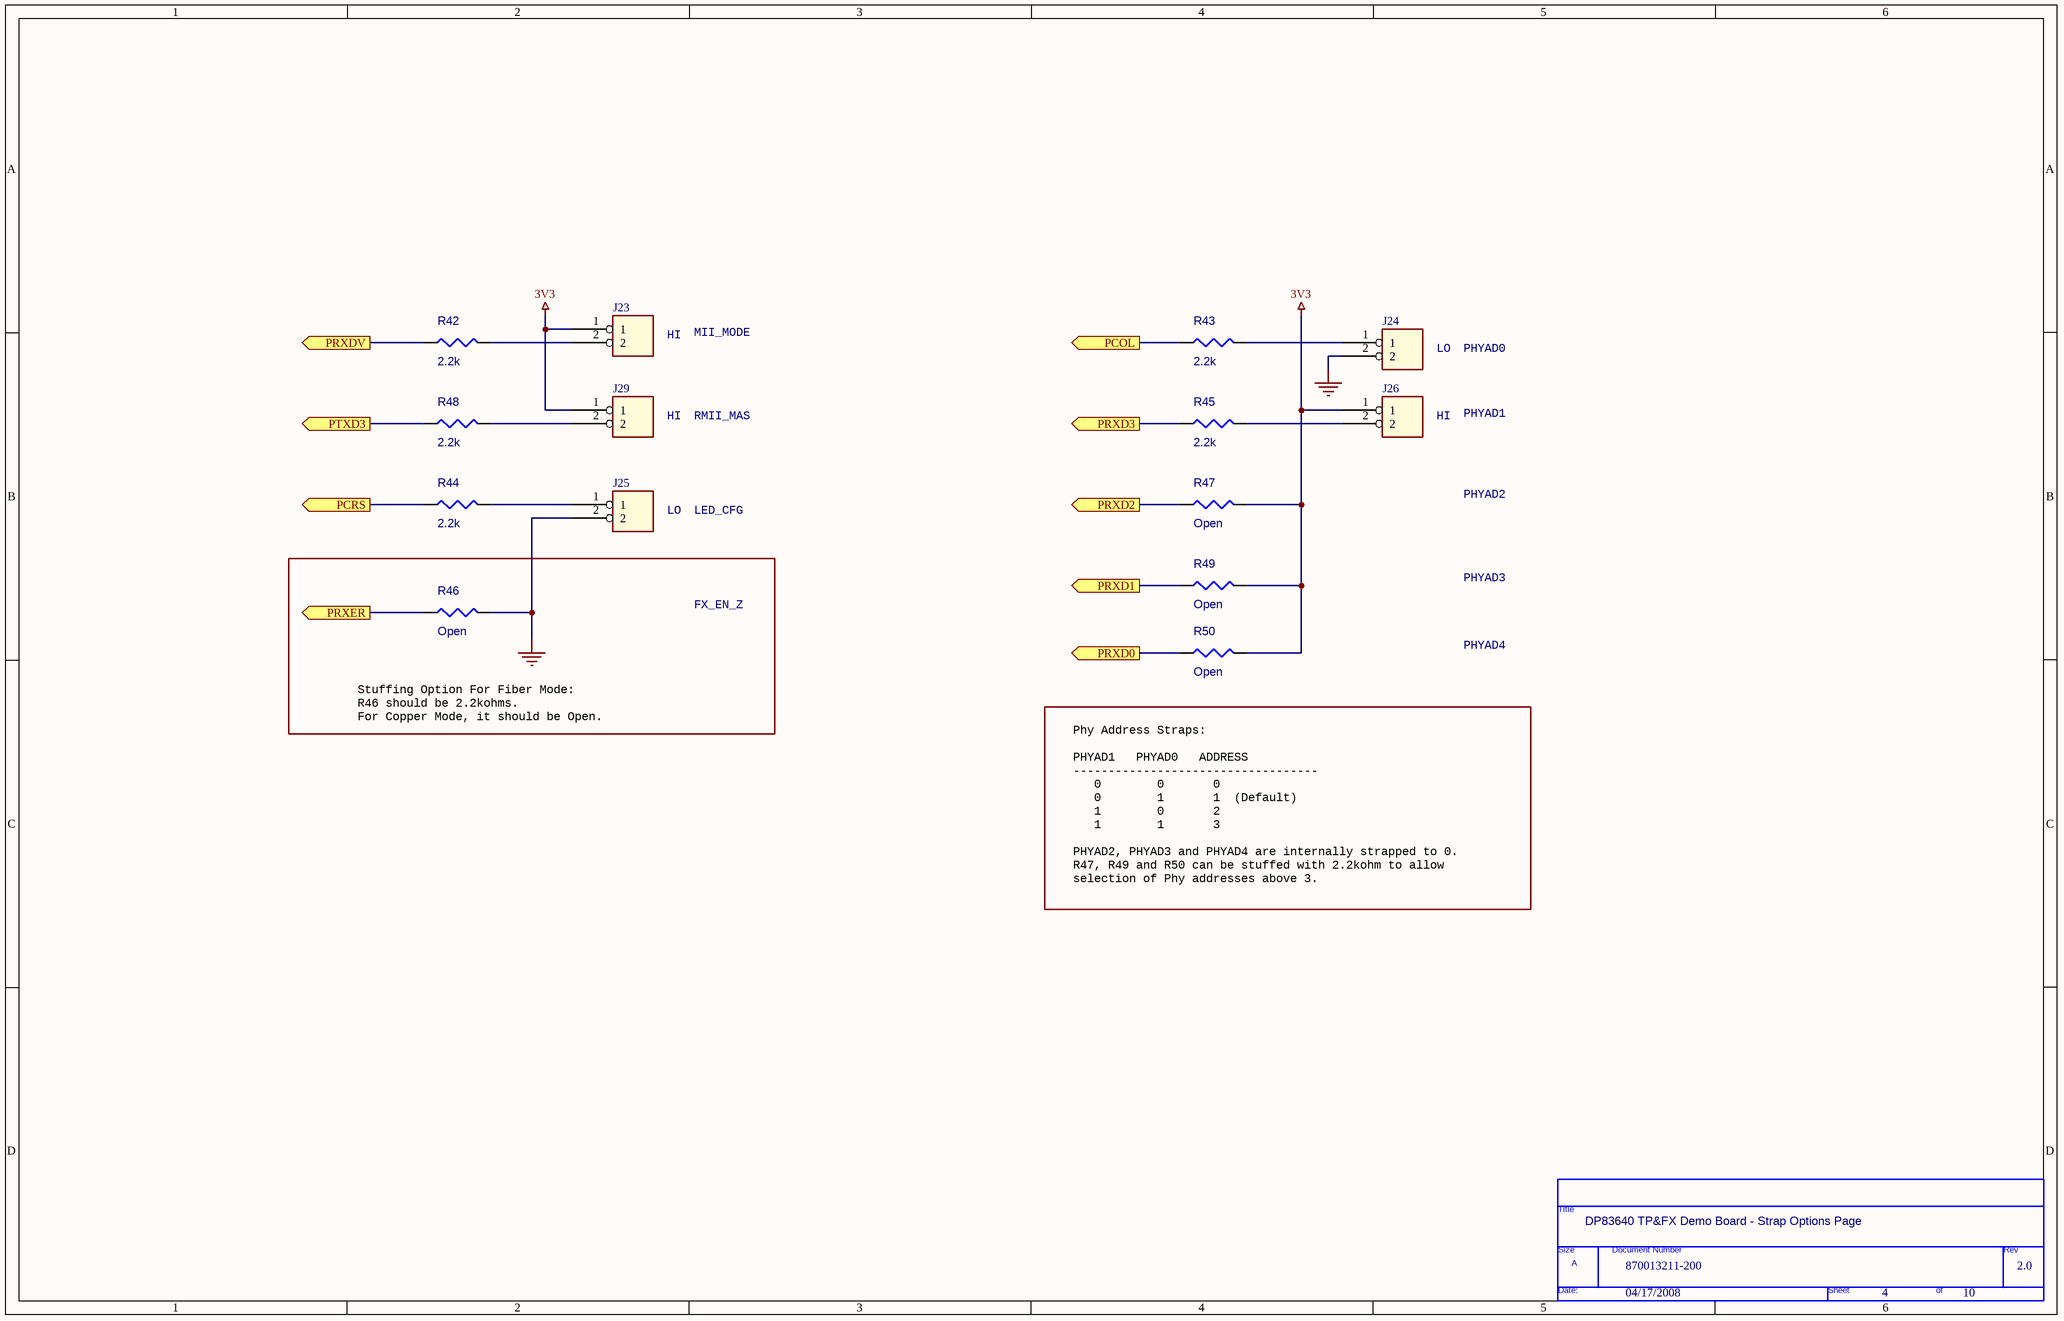
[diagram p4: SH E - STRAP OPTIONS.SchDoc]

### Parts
(Parts that share a designator on the sheet are numbered #1, #2 ... from top to bottom, then left to right.)
*#5  Title: DP83640 TP&FX Demo Board - Strap Options Page  Page Size: A  (hidden comment: TitleBlock0)  (graphical)
J23  HDR-1X2  [CN-HDR1X2]  (value not drawn)
J24  HDR-1X2  [CN-HDR1X2]  (value not drawn)
J25  HDR-1X2  [CN-HDR1X2]  (value not drawn)
J26  HDR-1X2  [CN-HDR1X2]  (value not drawn)
J29  HDR-1X2  [CN-HDR1X2]  (value not drawn)
R42  2.2k  [SMD0603-A-1]
R43  2.2k  [SMD0603-A-1]
R44  2.2k  [SMD0603-A-1]
R45  2.2k  [SMD0603-A-1]
R46  Open  [SMD0603-A-1]
R47  Open  [SMD0603-A-1]
R48  2.2k  [SMD0603-A-1]
R49  Open  [SMD0603-A-1]
R50  Open  [SMD0603-A-1]

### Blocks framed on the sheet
FX_EN_Z: R46

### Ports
PCOL (out), PCRS (out), PRXD0 (out), PRXD1 (out), PRXD2 (out), PRXD3 (out), PRXDV (out), PRXER (out), PTXD3 (out)

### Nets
3V3: J23.1 J26.1 J29.1 R47.2 R49.2 R50.2
GND: J24.2 J25.2 R46.2
PCOL: R43.1 ; port PCOL
PCRS: R44.1 ; port PCRS
PRXD0: R50.1 ; port PRXD0
PRXD1: R49.1 ; port PRXD1
PRXD2: R47.1 ; port PRXD2
PRXD3: R45.1 ; port PRXD3
PRXDV: R42.1 ; port PRXDV
PRXER: R46.1 ; port PRXER
PTXD3: R48.1 ; port PTXD3
NetJ23_2: J23.2 R42.2
NetJ24_1: J24.1 R43.2
NetJ25_1: J25.1 R44.2
NetJ26_2: J26.2 R45.2
NetJ29_2: J29.2 R48.2

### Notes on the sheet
- HI
- MII_MODE
- LO
- PHYAD0
- RMII_MAS
- PHYAD1
- LED_CFG
- PHYAD2
- PHYAD3
- PHYAD4
- Stuffing Option For Fiber Mode:
  R46 should be 2.2kohms.
  For Copper Mode, it should be Open.
- Phy Address Straps:
  PHYAD1   PHYAD0   ADDRESS
  -----------------------------------
  0        0       0
  0        1       1  (Default)
  1        0       2
  1        1       3
  PHYAD2, PHYAD3 and PHYAD4 are internally strapped to 0.
  R47, R49 and R50 can be stuffed with 2.2kohm to allow
  selection of Phy addresses above 3.

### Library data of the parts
R42-R50 = R: as R4 on sheet SH B - HP

## Sheet SH F - GPIO.SchDoc
size B; SheetNumber: 5; SheetTotal: 10; PageSetup: Record=PageOptions|CenterHorizontal=True|CenterVertical=True|PrintScale=1.09|XCorrection=1.00|YCorrection=1.00|PrintKind=1|BorderSize=5000000|LeftOffset=0|BottomOffset=0|Orientation=2|PaperLength=1000|PaperWidth=1000|Scale=100|PaperSource=15|PrintQuality=600|MediaType=1|DitherType=10|PaperKind=11x17|PrintScaleMode=1
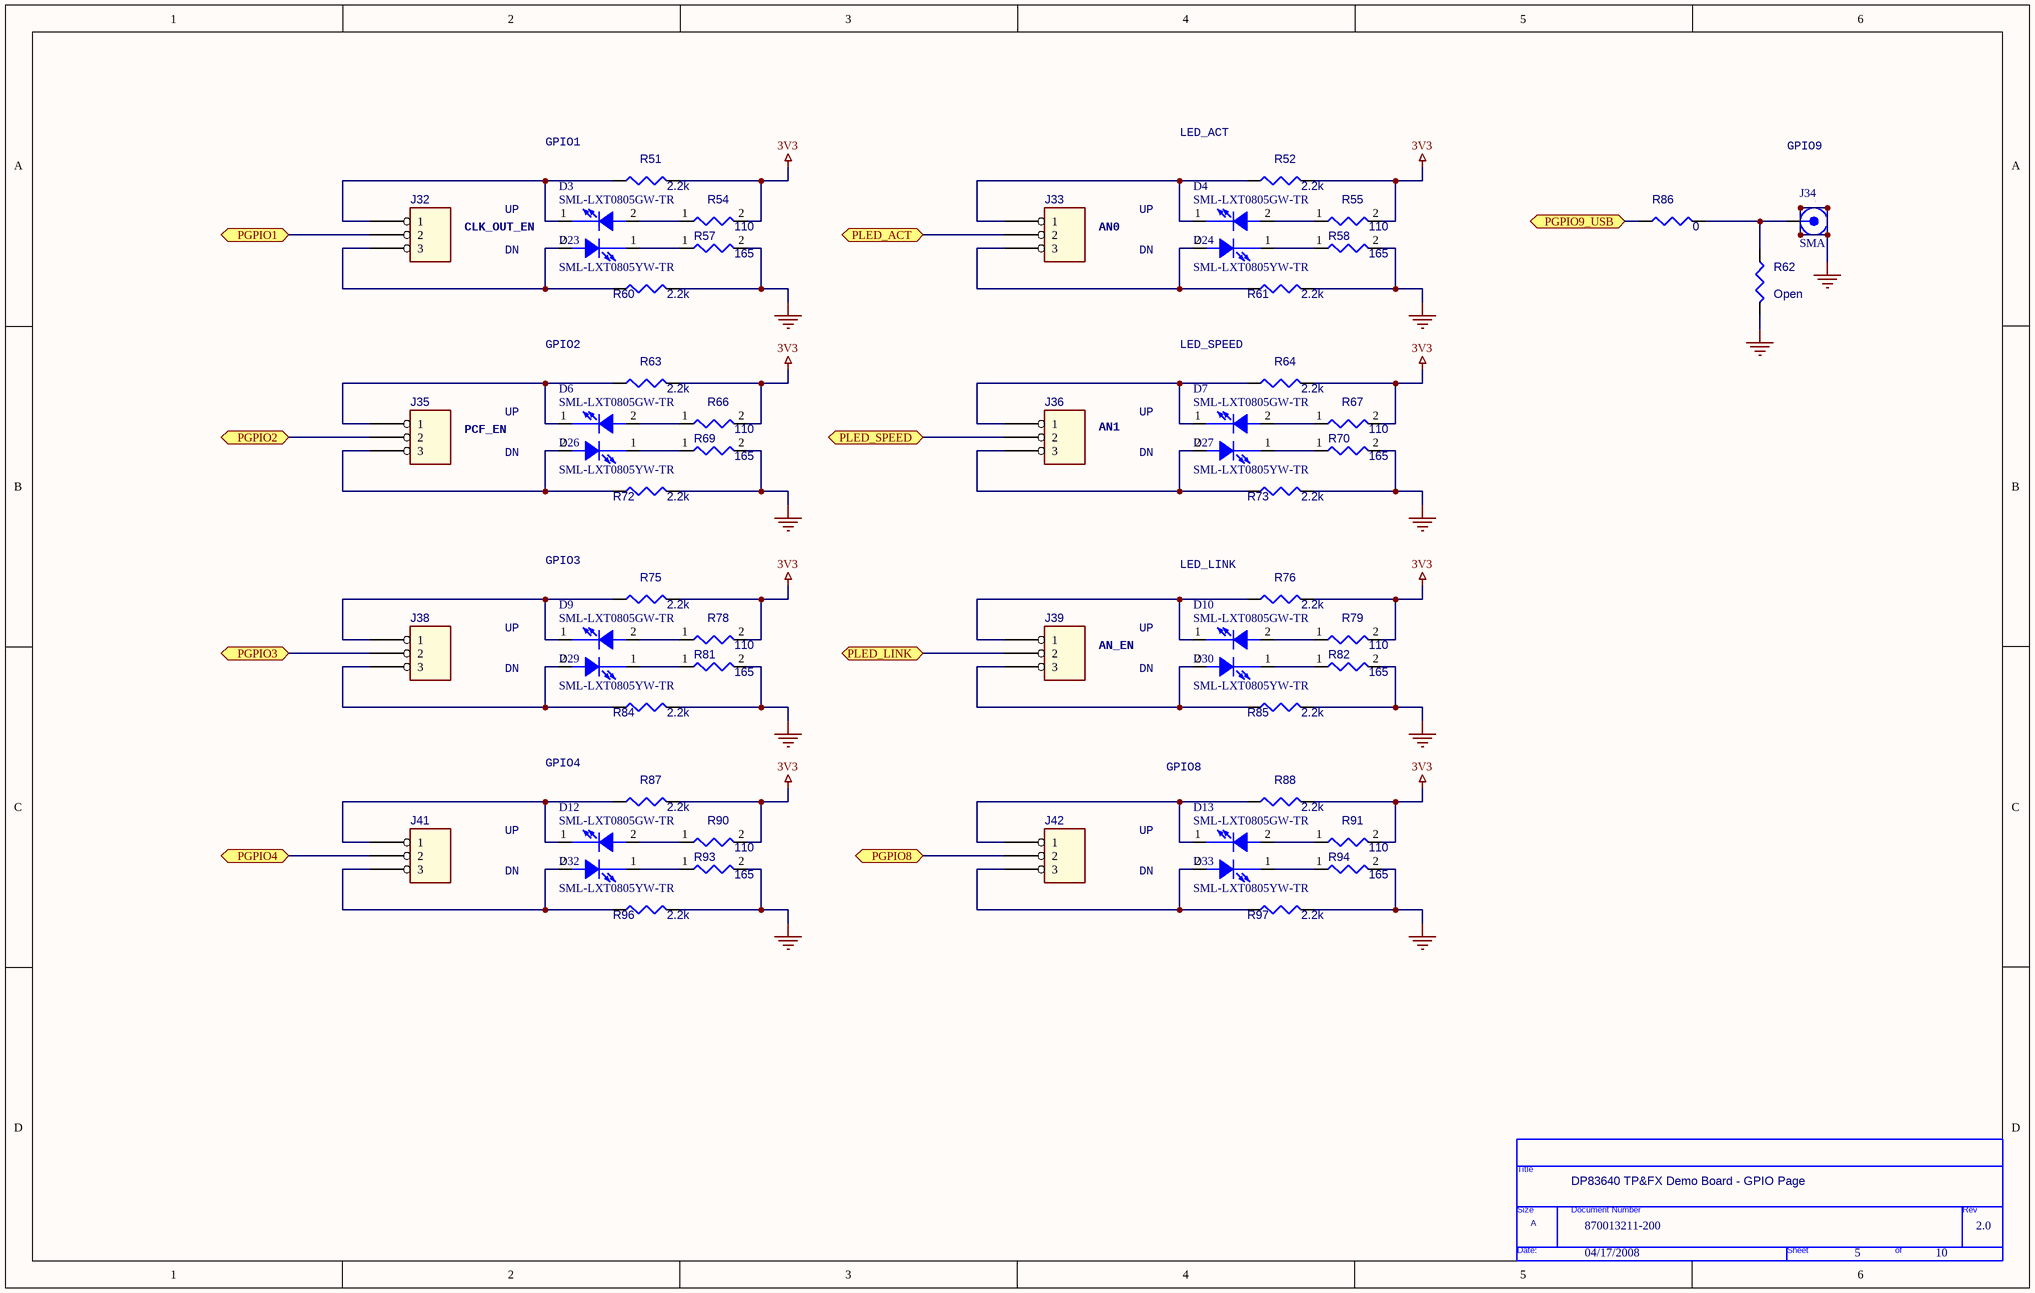
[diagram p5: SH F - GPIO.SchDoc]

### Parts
(Parts that share a designator on the sheet are numbered #1, #2 ... from top to bottom, then left to right.)
*#6  Title: DP83640 TP&FX Demo Board - GPIO Page  Page Size: A  (hidden comment: TitleBlock0)  (graphical)
D3  SML-LXT0805GW-TR  [SML-LXT0805]
D4  SML-LXT0805GW-TR  [SML-LXT0805]
D6  SML-LXT0805GW-TR  [SML-LXT0805]
D7  SML-LXT0805GW-TR  [SML-LXT0805]
D9  SML-LXT0805GW-TR  [SML-LXT0805]
D10  SML-LXT0805GW-TR  [SML-LXT0805]
D12  SML-LXT0805GW-TR  [SML-LXT0805]
D13  SML-LXT0805GW-TR  [SML-LXT0805]
D23  SML-LXT0805YW-TR  [SML-LXT0805]
D24  SML-LXT0805YW-TR  [SML-LXT0805]
D26  SML-LXT0805YW-TR  [SML-LXT0805]
D27  SML-LXT0805YW-TR  [SML-LXT0805]
D29  SML-LXT0805YW-TR  [SML-LXT0805]
D30  SML-LXT0805YW-TR  [SML-LXT0805]
D32  SML-LXT0805YW-TR  [SML-LXT0805]
D33  SML-LXT0805YW-TR  [SML-LXT0805]
J32  HDR_1X3  [CN-HDR1X3]  (value not drawn)
J33  HDR_1X3  [CN-HDR1X3]  (value not drawn)
J34  SMA  [J608-ND]
J35  HDR_1X3  [CN-HDR1X3]  (value not drawn)
J36  HDR_1X3  [CN-HDR1X3]  (value not drawn)
J38  HDR_1X3  [CN-HDR1X3]  (value not drawn)
J39  HDR_1X3  [CN-HDR1X3]  (value not drawn)
J41  HDR_1X3  [CN-HDR1X3]  (value not drawn)
J42  HDR_1X3  [CN-HDR1X3]  (value not drawn)
R51  2.2k  [SMD0603-A-1]
R52  2.2k  [SMD0603-A-1]
R54  110  [SMD0603-A-1]
R55  110  [SMD0603-A-1]
R57  165  [SMD0603-A-1]
R58  165  [SMD0603-A-1]
R60  2.2k  [SMD0603-A-1]
R61  2.2k  [SMD0603-A-1]
R62  Open  [SMD0603-A-1]
R63  2.2k  [SMD0603-A-1]
R64  2.2k  [SMD0603-A-1]
R66  110  [SMD0603-A-1]
R67  110  [SMD0603-A-1]
R69  165  [SMD0603-A-1]
R70  165  [SMD0603-A-1]
R72  2.2k  [SMD0603-A-1]
R73  2.2k  [SMD0603-A-1]
R75  2.2k  [SMD0603-A-1]
R76  2.2k  [SMD0603-A-1]
R78  110  [SMD0603-A-1]
R79  110  [SMD0603-A-1]
R81  165  [SMD0603-A-1]
R82  165  [SMD0603-A-1]
R84  2.2k  [SMD0603-A-1]
R85  2.2k  [SMD0603-A-1]
R86  0  [SMD0603-A-1]
R87  2.2k  [SMD0603-A-1]
R88  2.2k  [SMD0603-A-1]
R90  110  [SMD0603-A-1]
R91  110  [SMD0603-A-1]
R93  165  [SMD0603-A-1]
R94  165  [SMD0603-A-1]
R96  2.2k  [SMD0603-A-1]
R97  2.2k  [SMD0603-A-1]

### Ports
PGPIO1 (bidir), PGPIO2 (bidir), PGPIO3 (bidir), PGPIO4 (bidir), PGPIO8 (bidir), PGPIO9_USB (bidir), PLED_ACT (bidir), PLED_LINK (bidir), PLED_SPEED (bidir)

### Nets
3V3: R51.2 R52.2 R54.2 R55.2 R63.2 R64.2 R66.2 R67.2 R75.2 R76.2 R78.2 R79.2 R87.2 R88.2 R90.2 R91.2
GND: J34.2(GND2) J34.3(GND3) J34.4(GND4) J34.5(GND5) R57.2 R58.2 R60.2 R61.2 R62.2 R69.2 R70.2 R72.2 R73.2 R81.2 R82.2 R84.2 R85.2 R93.2 R94.2 R96.2 R97.2
NetD3_1: D3.1(Cathode) J32.1 R51.1
NetD3_2: D3.2(Anode) R54.1
NetD4_1: D4.1(Cathode) J33.1 R52.1
NetD4_2: D4.2(Anode) R55.1
NetD6_1: D6.1(Cathode) J35.1 R63.1
NetD6_2: D6.2(Anode) R66.1
NetD7_1: D7.1(Cathode) J36.1 R64.1
NetD7_2: D7.2(Anode) R67.1
NetD9_1: D9.1(Cathode) J38.1 R75.1
NetD9_2: D9.2(Anode) R78.1
NetD10_1: D10.1(Cathode) J39.1 R76.1
NetD10_2: D10.2(Anode) R79.1
NetD12_1: D12.1(Cathode) J41.1 R87.1
NetD12_2: D12.2(Anode) R90.1
NetD13_1: D13.1(Cathode) J42.1 R88.1
NetD13_2: D13.2(Anode) R91.1
NetD23_1: D23.1(Cathode) R57.1
NetD23_2: D23.2(Anode) J32.3 R60.1
NetD24_1: D24.1(Cathode) R58.1
NetD24_2: D24.2(Anode) J33.3 R61.1
NetD26_1: D26.1(Cathode) R69.1
NetD26_2: D26.2(Anode) J35.3 R72.1
NetD27_1: D27.1(Cathode) R70.1
NetD27_2: D27.2(Anode) J36.3 R73.1
NetD29_1: D29.1(Cathode) R81.1
NetD29_2: D29.2(Anode) J38.3 R84.1
NetD30_1: D30.1(Cathode) R82.1
NetD30_2: D30.2(Anode) J39.3 R85.1
NetD32_1: D32.1(Cathode) R93.1
NetD32_2: D32.2(Anode) J41.3 R96.1
NetD33_1: D33.1(Cathode) R94.1
NetD33_2: D33.2(Anode) J42.3 R97.1
NetJ1_1: J32.2 ; port PGPIO1
NetJ1_3: J35.2 ; port PGPIO2
NetJ1_5: J38.2 ; port PGPIO3
NetJ1_7: J41.2 ; port PGPIO4
NetJ1_9: J33.2 ; port PLED_ACT
NetJ1_11: J36.2 ; port PLED_SPEED
NetJ1_13: J39.2 ; port PLED_LINK
NetJ1_15: J42.2 ; port PGPIO8
NetJ1_17: R86.1 ; port PGPIO9_USB
NetJ34_1: J34.1 R62.1 R86.2

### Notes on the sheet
- GPIO1
- LED_ACT
- GPIO9
- CLK_OUT_EN
- UP
- AN0
- DN
- GPIO2
- LED_SPEED
- PCF_EN
- AN1
- GPIO3
- (near R76) LED_LINK
- AN_EN
- GPIO4
- GPIO8

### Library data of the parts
D3 D4 D6 D7 D9 D10 D12 D13 = LED SML-LXT0805GW-TR
D23 D24 D26 D27 D29 D30 D32 D33 = LED SML-LXT0805YW-TR
J32 J33 J35 J36 J38 J39 J41 J42 = HDR_1X3_Dup1
J34 = SMA_1
R51 R52 R60-R64 R72 R73 R75 R76 R84-R88 R96 R97 = R: as R4 on sheet SH B - HP
R54 R55 R57 R58 R66 R67 R69 R70 R78 R79 R81 R82 R90 R91 R93 R94 = R: Part Description: RES, SMD, 0603; Tolerance: 1%; Power: 1/16W

## Sheet SH G - TP Integrated Magnetics.SchDoc
size 386 x 246 mm; SheetNumber: 6; SheetTotal: 10
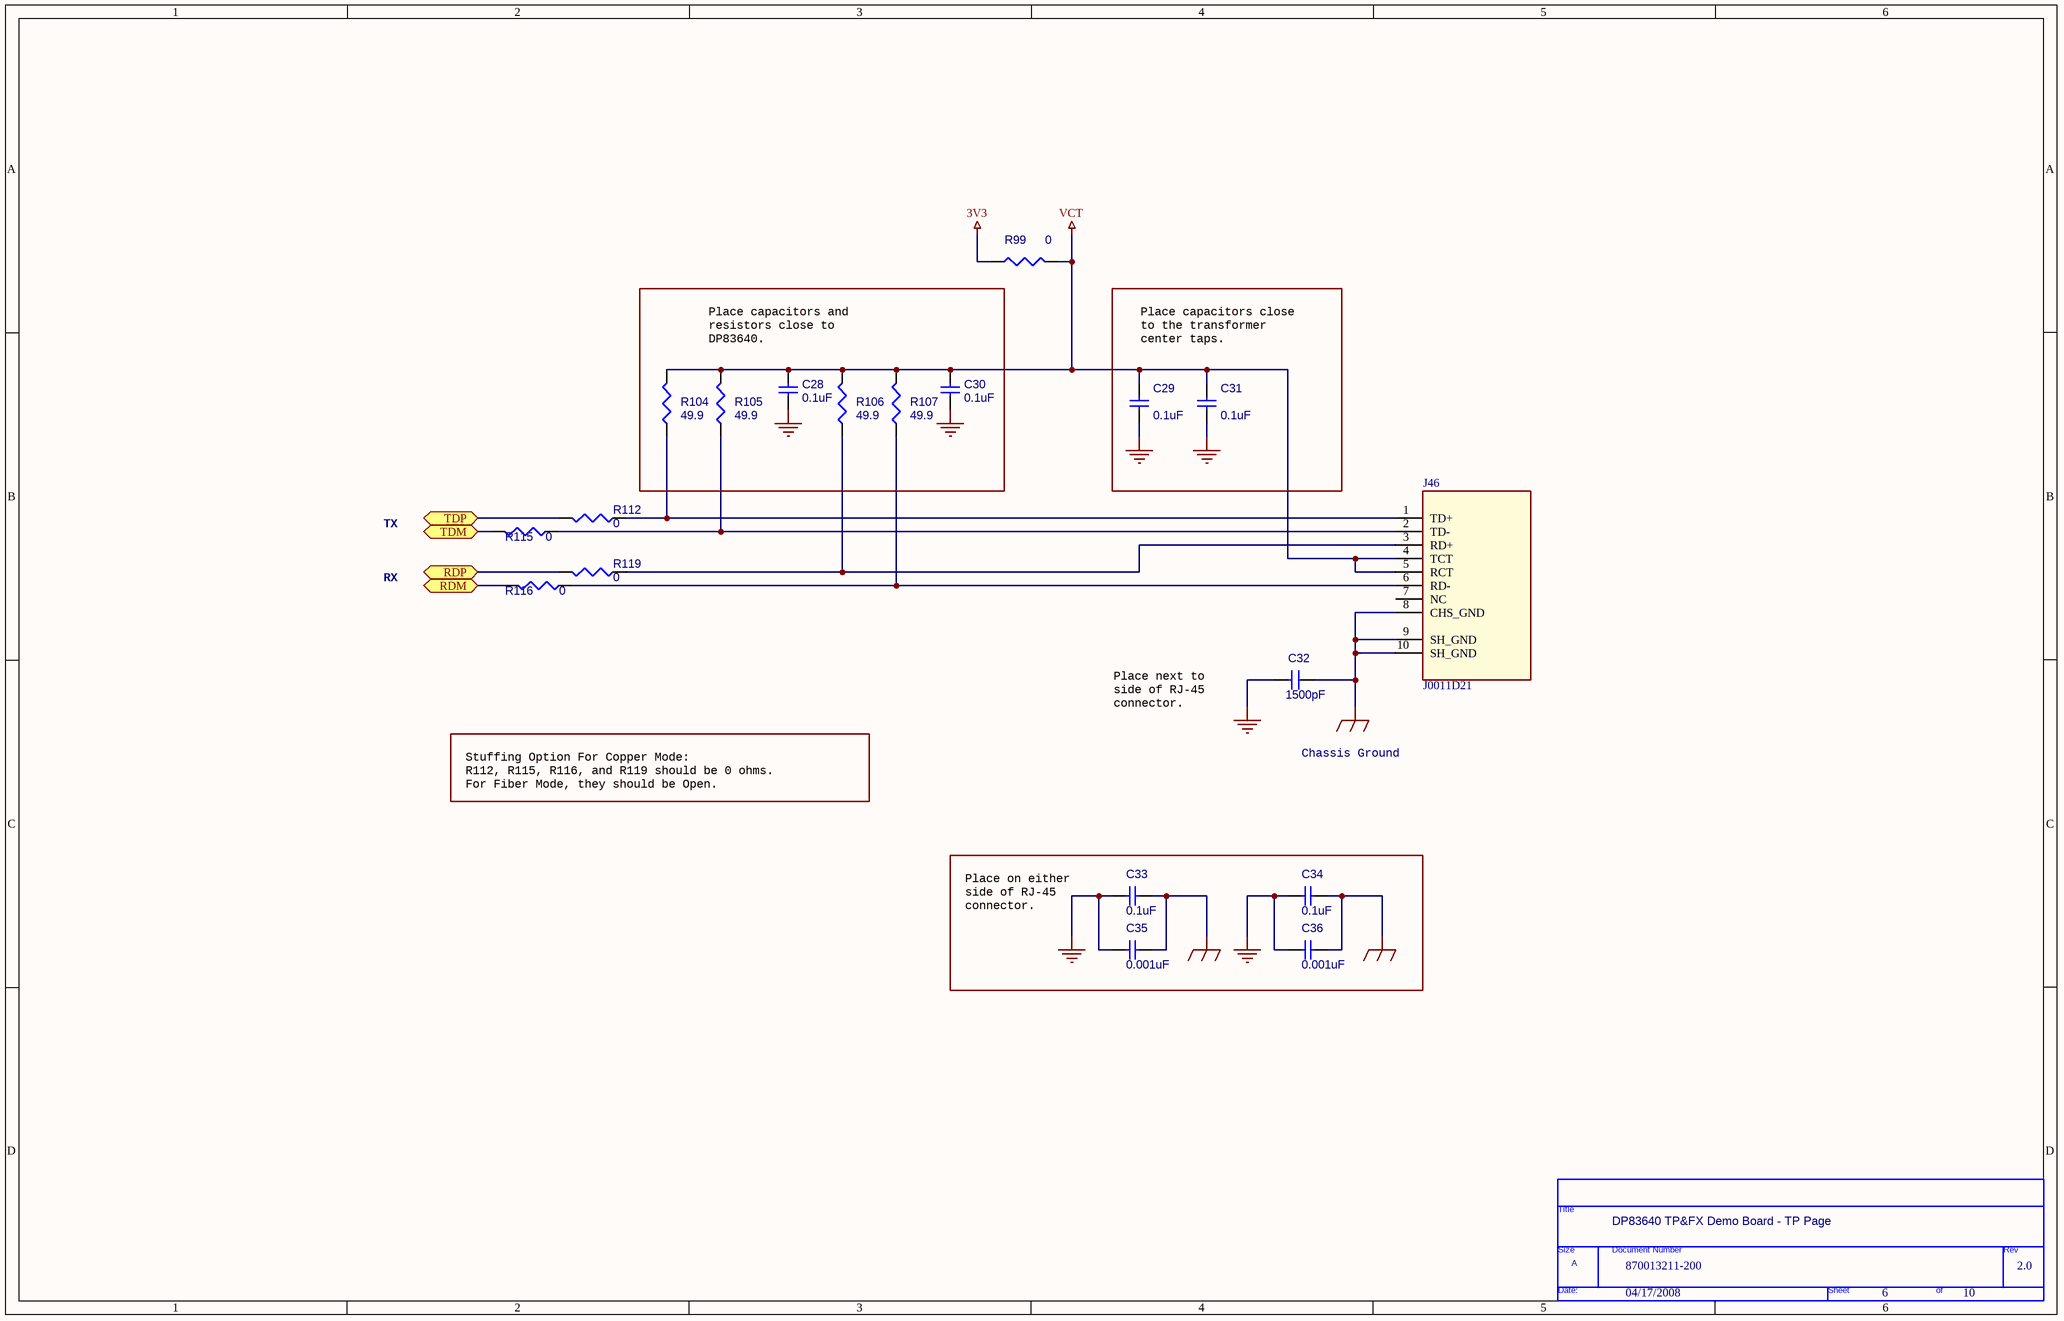
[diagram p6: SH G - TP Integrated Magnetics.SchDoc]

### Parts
(Parts that share a designator on the sheet are numbered #1, #2 ... from top to bottom, then left to right.)
*#7  Title: DP83640 TP&FX Demo Board - TP Page  Page Size: A  (hidden comment: TitleBlock0)  (graphical)
C28  0.1uF  [SMD0603-A-1]
C29  0.1uF  [SMD0603-A-1]
C30  0.1uF  [SMD0603-A-1]
C31  0.1uF  [SMD0603-A-1]
C32  1500pF  [SMD1808-A-1]
C33  0.1uF  [SMD0603-A-1]
C34  0.1uF  [SMD0603-A-1]
C35  0.001uF  [SMD0603-A-1]
C36  0.001uF  [SMD0603-A-1]
J46  J0011D21  [J0011D21]
R99  0  [SMD0603-A-1]
R104  49.9  [SMD0603-A-1]
R105  49.9  [SMD0603-A-1]
R106  49.9  [SMD0603-A-1]
R107  49.9  [SMD0603-A-1]
R112  0  [SMD0603-A-1]
R115  0  [SMD0603-A-1]
R116  0  [SMD0603-A-1]
R119  0  [SMD0603-A-1]

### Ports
RDM (bidir), RDP (bidir), TDM (bidir), TDP (bidir)

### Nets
3V3: R99.1
GND: C28.1 C29.2 C30.1 C31.2 C32.2 C33.1 C34.1 C35.1 C36.1
GND_Chassis: C32.1 C33.2 C34.2 C35.2 C36.2 J46.8(CHS_GND) J46.9(SH_GND) J46.10(SH_GND)
VCT: C28.2 C29.1 C30.2 C31.1 J46.4(TCT) J46.5(RCT) R99.2 R104.2 R105.2 R106.2 R107.2
NetJ46_1: J46.1(TD+) R104.1 R112.2
NetJ46_2: J46.2(TD-) R105.1 R115.1
NetJ46_3: J46.3(RD+) R106.1 R119.2
NetJ46_6: J46.6(RD-) R107.1 R116.1
NetR112_1: R112.1 ; port TDP
NetR114_2: R115.2 ; port TDM
NetR116_2: R116.2 ; port RDM
NetR118_2: R119.1 ; port RDP

Not connected (* = marked no-connect by the designer): J46 7(NC)

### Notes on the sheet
- Place capacitors and resistors close to DP83640.
- Place capacitors close to the transformer center taps.
- TX
- RX
- Place next to  side of RJ-45 connector.
- Stuffing Option For Copper Mode:
  R112, R115, R116, and R119 should be 0 ohms.
  For Fiber Mode, they should be Open.
- Chassis Ground
- Place on either side of RJ-45 connector.

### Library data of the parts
C28-C31 = C-0_0.1uF: Part Description: CAP, SMD, Ceramic, 0603; Tolerance: +80-20%; Voltage: 50V
C32 = SMALL CAP: Part Description: CAP, SMD, Ceramic, 1808; Voltage: 2KV; Tolerance: 10%
C33-C36 = C-0_0.1uF: as C2 on sheet SH B - HP
J46 = PulseJack RJ45 J0011D21
R99 R112 R115 R116 R119 = R: as R1 on sheet SH B - HP
R104-R107 = R: as R54 on sheet SH F - GPIO

## Sheet SH H - zFX.SchDoc
size 386 x 246 mm; SheetNumber: 7; SheetTotal: 10
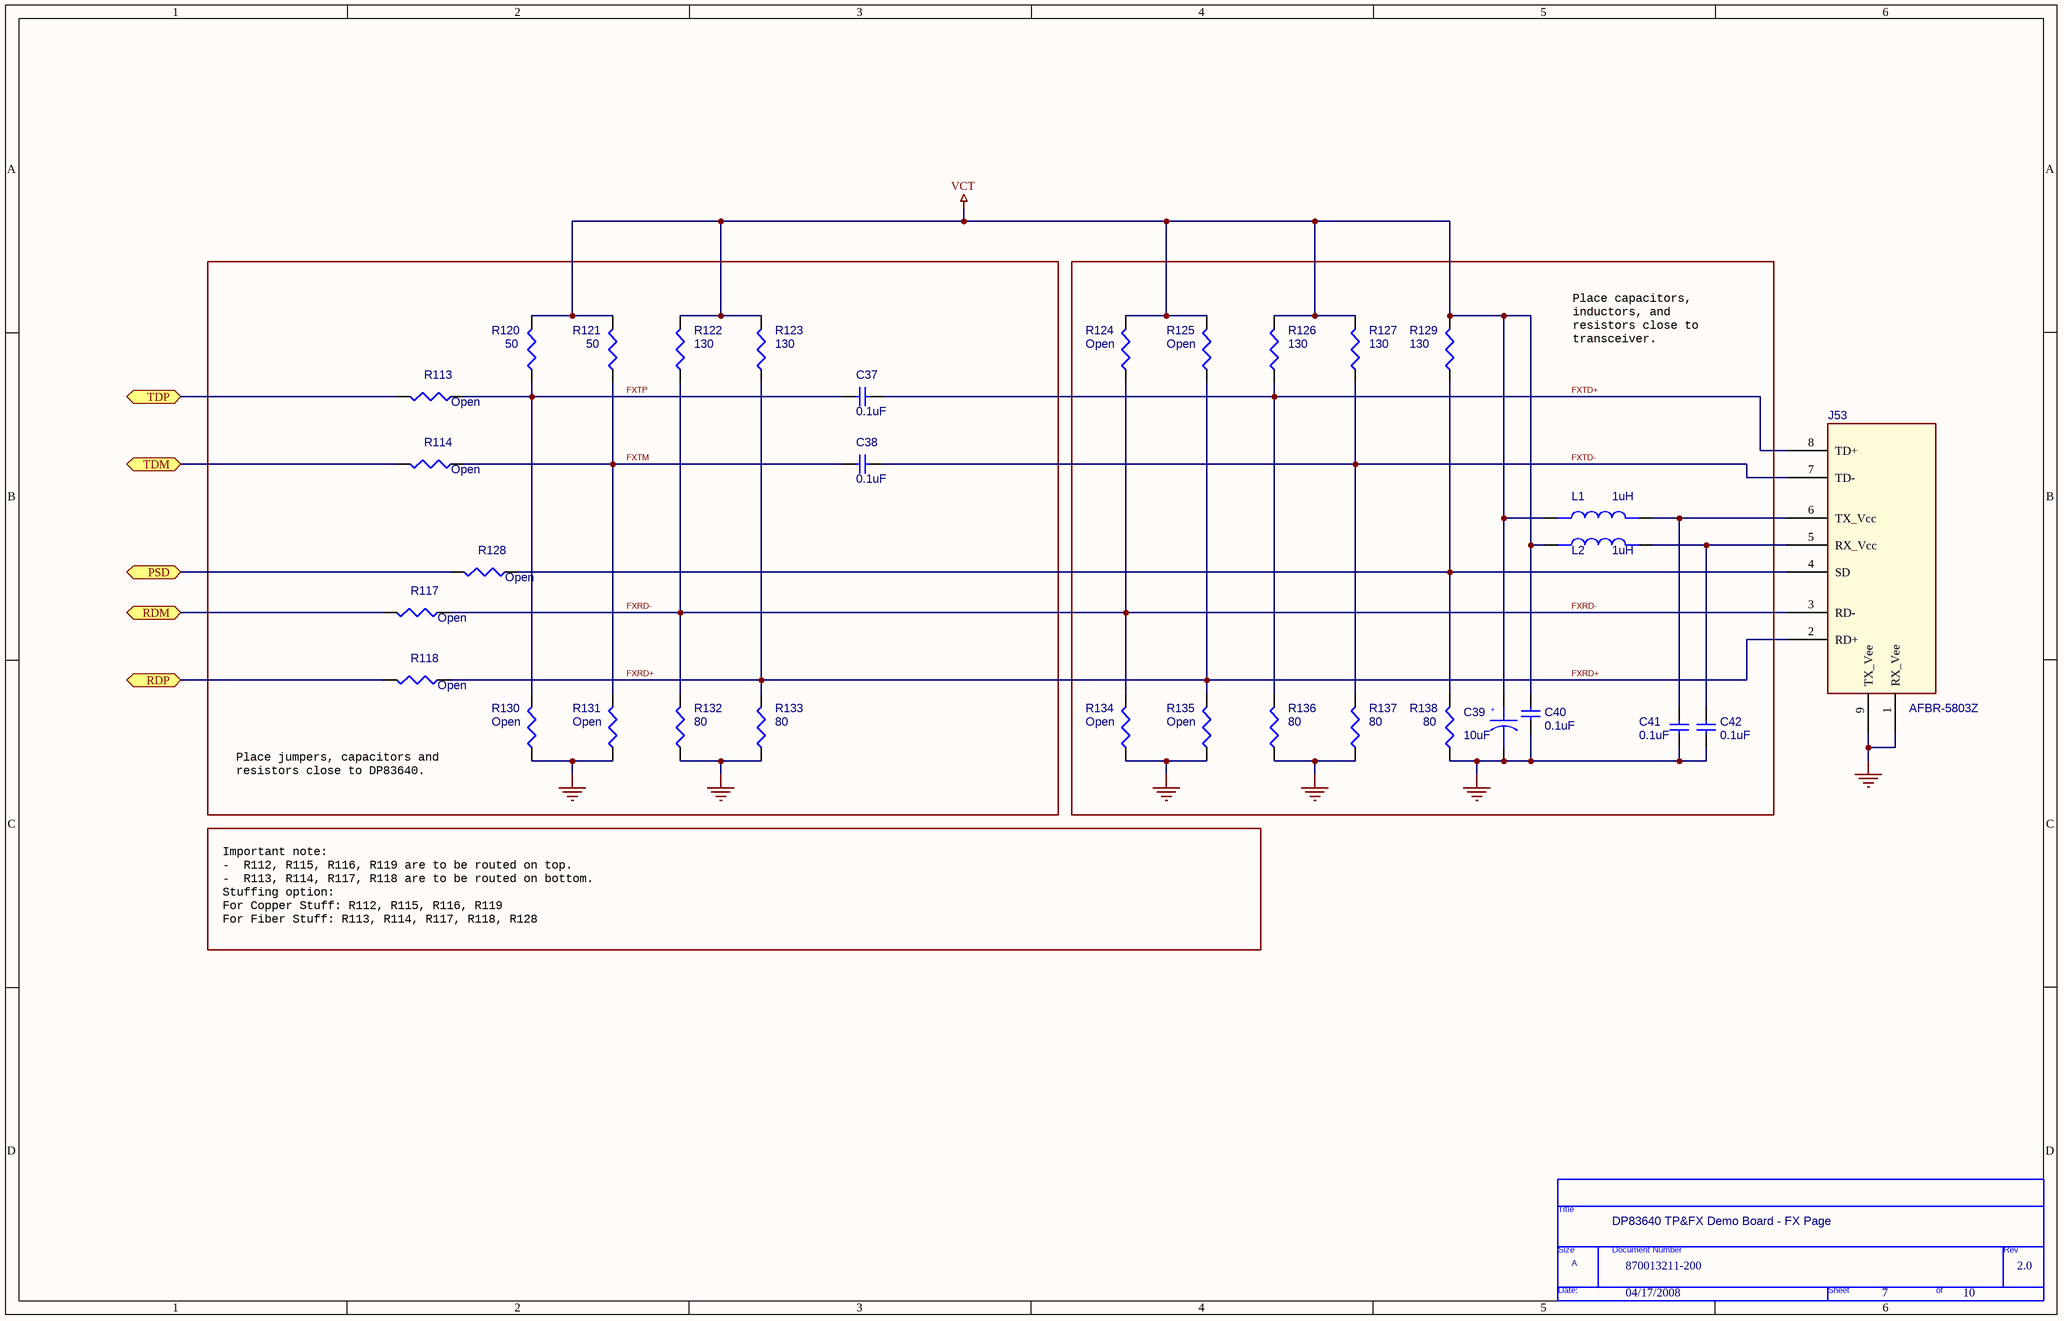
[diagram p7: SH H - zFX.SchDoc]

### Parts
(Parts that share a designator on the sheet are numbered #1, #2 ... from top to bottom, then left to right.)
*#8  Title: DP83640 TP&FX Demo Board - FX Page  Page Size: A  (hidden comment: TitleBlock0)  (graphical)
C37  0.1uF  [SMD0603-A-1]
C38  0.1uF  [SMD0603-A-1]
C39  10uF  [SMD3528-B-1]
C40  0.1uF  [SMD0603-A-1]
C41  0.1uF  [SMD0603-A-1]
C42  0.1uF  [SMD0603-A-1]
J53  AFBR-5803Z  [HFBR-5803 SC Connector]
L1  1uH  [Murata LQM18N Series]
L2  1uH  [Murata LQM18N Series]
R113  Open  [SMD0603-A-1]
R114  Open  [SMD0603-A-1]
R117  Open  [SMD0603-A-1]
R118  Open  [SMD0603-A-1]
R120  50  [SMD0603-A-1]
R121  50  [SMD0603-A-1]
R122  130  [SMD0603-A-1]
R123  130  [SMD0603-A-1]
R124  Open  [SMD0603-A-1]
R125  Open  [SMD0603-A-1]
R126  130  [SMD0603-A-1]
R127  130  [SMD0603-A-1]
R128  Open  [SMD0603-A-1]
R129  130  [SMD0603-A-1]
R130  Open  [SMD0603-A-1]
R131  Open  [SMD0603-A-1]
R132  80  [SMD0603-A-1]
R133  80  [SMD0603-A-1]
R134  Open  [SMD0603-A-1]
R135  Open  [SMD0603-A-1]
R136  80  [SMD0603-A-1]
R137  80  [SMD0603-A-1]
R138  80  [SMD0603-A-1]

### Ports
PSD (bidir), RDM (bidir), RDP (bidir), TDM (bidir), TDP (bidir)

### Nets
GND: C39.2 C40.2 C41.1 C42.1 J53.1(RX_Vee) J53.9(TX_Vee) R130.1 R131.1 R132.1 R133.1 R134.1 R135.1 R136.1 R137.1 R138.1
VCT: C39.1 C40.1 L1.1 L2.1 R120.2 R121.2 R122.2 R123.2 R124.2 R125.2 R126.2 R127.2 R129.2
FXRD+: J53.2(RD+) R118.1 R123.1 R125.1 R133.2 R135.2
FXRD-: J53.3(RD-) R117.1 R122.1 R124.1 R132.2 R134.2
FXTD+: C37.1 J53.8(TD+) R126.1 R136.2
FXTD-: C38.1 J53.7(TD-) R127.1 R137.2
FXTM: C38.2 R114.1 R121.1 R131.2
FXTP: C37.2 R113.1 R120.1 R130.2
NetC41_2: C41.2 J53.6(TX_Vcc) L1.2
NetC42_2: C42.2 J53.5(RX_Vcc) L2.2
NetJ53_4: J53.4(SD) R128.2 R129.1 R138.2
NetR112_1: R113.2 ; port TDP
NetR114_2: R114.2 ; port TDM
NetR116_2: R117.2 ; port RDM
NetR118_2: R118.2 ; port RDP
NetR128_1: R128.1 ; port PSD

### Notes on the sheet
- Place capacitors, inductors, and resistors close to transceiver.
- Place jumpers, capacitors and resistors close to DP83640.
- Important note:
  -  R112, R115, R116, R119 are to be routed on top.
  -  R113, R114, R117, R118 are to be routed on bottom.
  Stuffing option:
  For Copper Stuff: R112, R115, R116, R119
  For Fiber Stuff: R113, R114, R117, R118, R128

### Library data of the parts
C37 C38 C40-C42 = C-0_0.1uF: as C2 on sheet SH B - HP
C39 = 10uF: Part Description: CAP, SMD, Tant, 3528; Voltage: 16V; Tolerance: 10%
J53 = HFBR-5803_6
L1 L2 = 1uH: Part Description: LQM18NN1R0K00D Ferrite Inductor; Manufacturer: Murata LQM18NN1R0K00D
R113 R114 R117 R118 R120-R138 = R: as R1 on sheet SH B - HP

## Sheet SH I - MII.SchDoc
size 386 x 246 mm; SheetNumber: 8; SheetTotal: 10
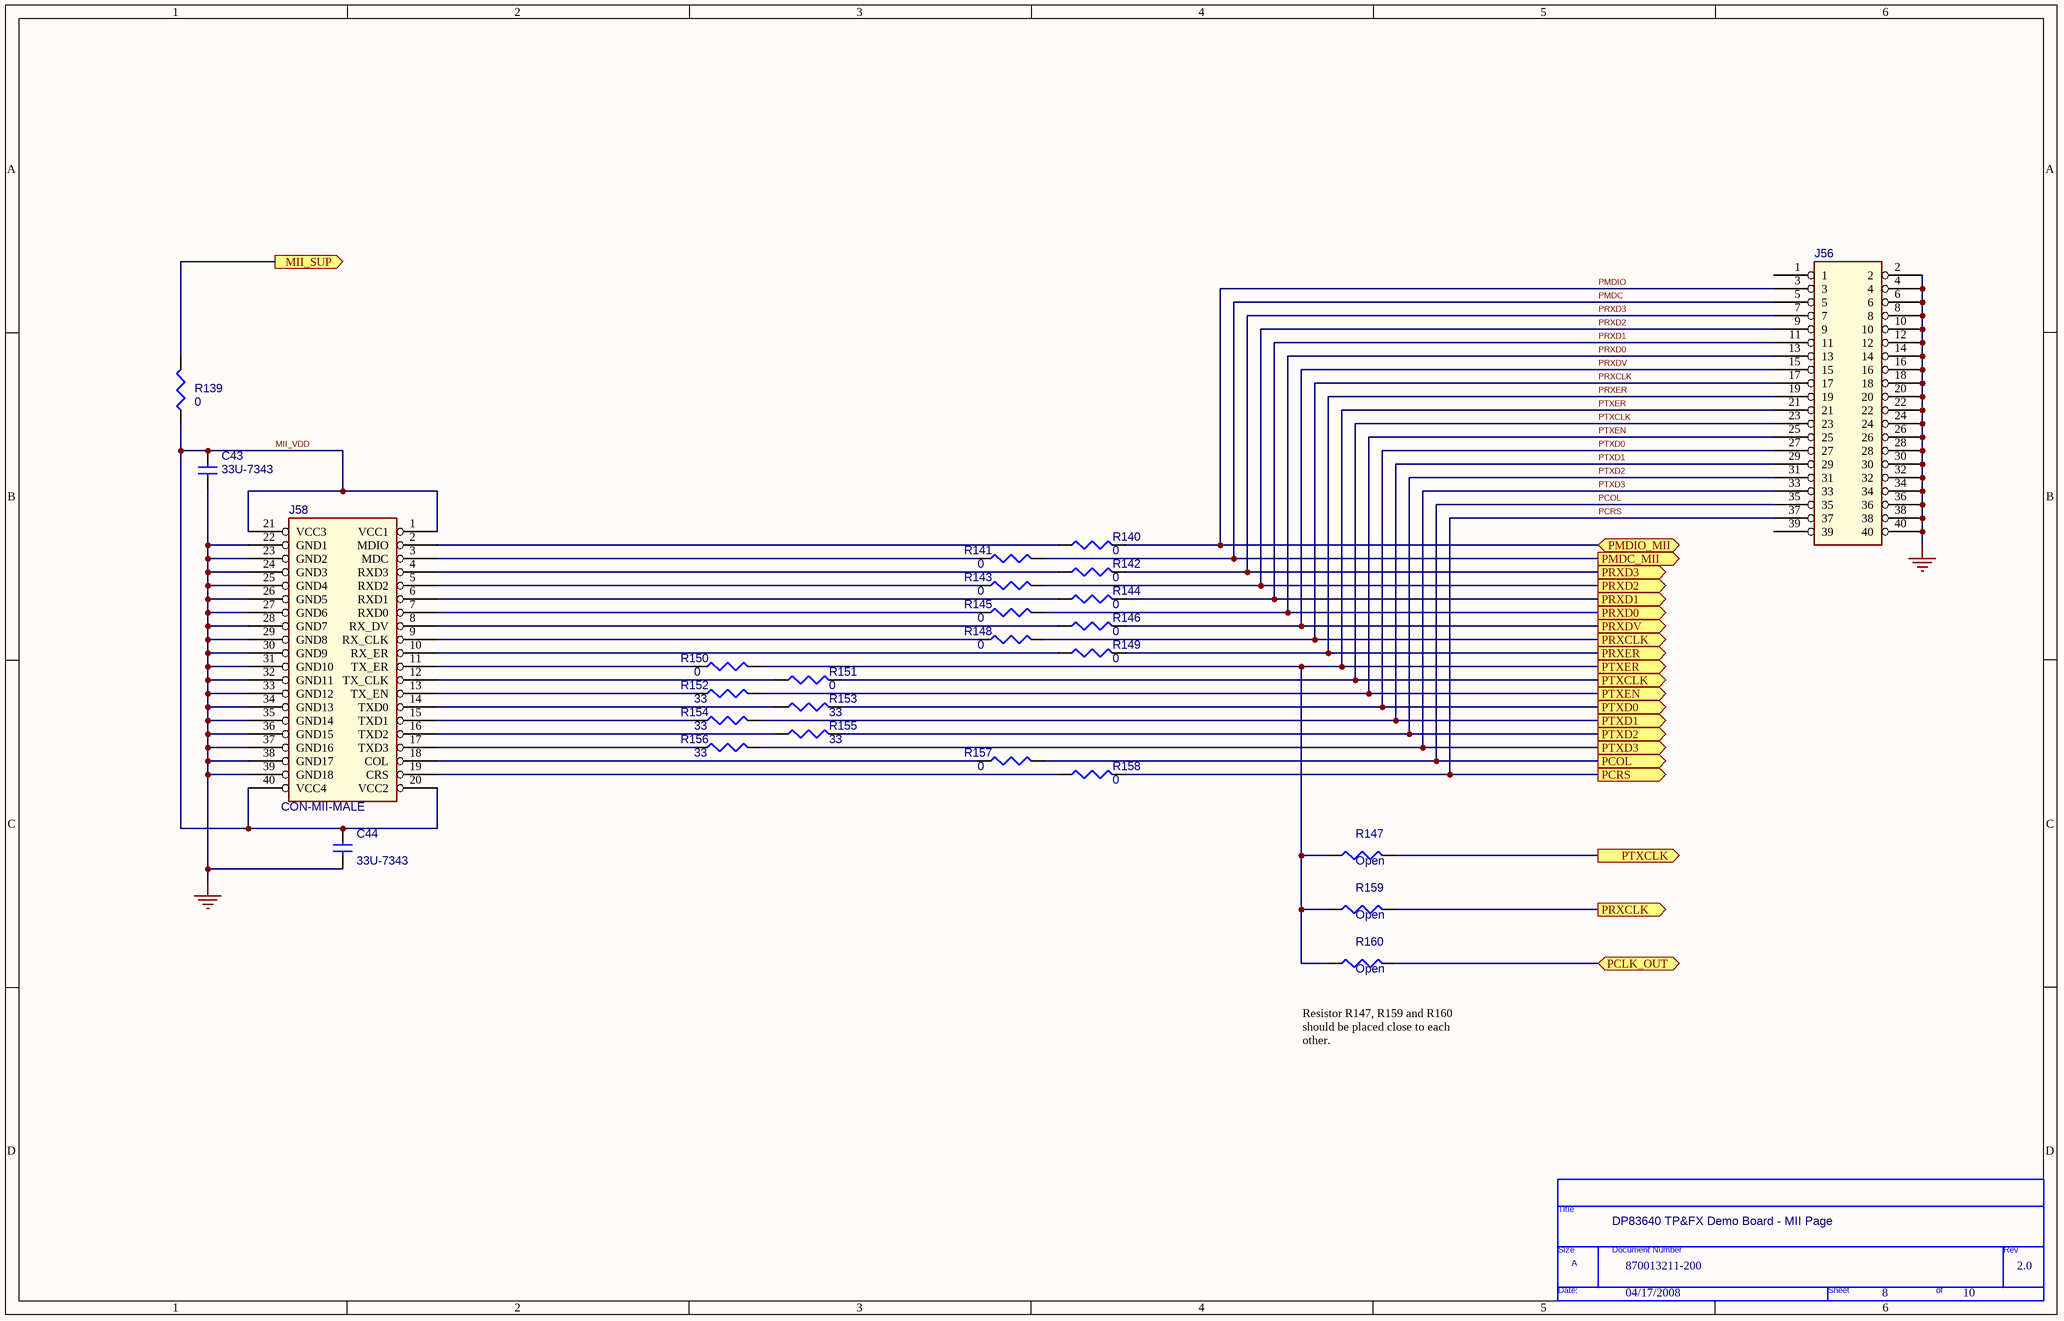
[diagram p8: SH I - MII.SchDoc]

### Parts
(Parts that share a designator on the sheet are numbered #1, #2 ... from top to bottom, then left to right.)
*#9  Title: DP83640 TP&FX Demo Board - MII Page  Page Size: A  (hidden comment: TitleBlock0)  (graphical)
C43  33U-7343  [SMD07343]
C44  33U-7343  [SMD07343]
J56  HDR-2X20  [CN-HDR2X20]  (value not drawn)
J58  CON-MII-MALE  [CN-MII-40P-RA-M]
R139  0  [SMD0603-A-1]
R140  0  [SMD0603-A-1]
R141  0  [SMD0603-A-1]
R142  0  [SMD0603-A-1]
R143  0  [SMD0603-A-1]
R144  0  [SMD0603-A-1]
R145  0  [SMD0603-A-1]
R146  0  [SMD0603-A-1]
R147  Open  [SMD0603-A-1]
R148  0  [SMD0603-A-1]
R149  0  [SMD0603-A-1]
R150  0  [SMD0603-A-1]
R151  0  [SMD0603-A-1]
R152  33  [SMD0603-A-1]
R153  33  [SMD0603-A-1]
R154  33  [SMD0603-A-1]
R155  33  [SMD0603-A-1]
R156  33  [SMD0603-A-1]
R157  0  [SMD0603-A-1]
R158  0  [SMD0603-A-1]
R159  Open  [SMD0603-A-1]
R160  Open  [SMD0603-A-1]

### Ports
MII_SUP (out), PCLK_OUT (bidir), PCOL (out), PCRS (out), PMDC_MII (out), PMDIO_MII (bidir), PRXCLK (out), PRXD0 (out), PRXD1 (out), PRXD2 (out), PRXD3 (out), PRXDV (out), PRXER (out), PTXCLK (out), PTXD0 (out), PTXD1 (out), PTXD2 (out), PTXD3 (out), PTXEN (out), PTXER (out)

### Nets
GND: C43.2 C44.2 J56.2 J56.4 J56.6 J56.8 J56.10 J56.12 J56.14 J56.16 J56.18 J56.20 J56.22 J56.24 J56.26 J56.28 J56.30 J56.32 J56.34 J56.36 J56.38 J56.40 J58.22(GND1) J58.23(GND2) J58.24(GND3) J58.25(GND4) J58.26(GND5) J58.27(GND6) J58.28(GND7) J58.29(GND8) J58.30(GND9) J58.31(GND10) J58.32(GND11) J58.33(GND12) J58.34(GND13) J58.35(GND14) J58.36(GND15) J58.37(GND16) J58.38(GND17) J58.39(GND18)
MII_VDD: C43.1 C44.1 J58.1(VCC1) J58.20(VCC2) J58.21(VCC3) J58.40(VCC4) R139.1
PCOL: J56.35 R157.1 ; port PCOL
PCRS: J56.37 R158.1 ; port PCRS
PMDC: J56.5 R141.1 ; port PMDC_MII
PMDIO: J56.3 R140.1 ; port PMDIO_MII
PRXCLK: J56.17 R148.1 R159.2 ; port PRXCLK
PRXD0: J56.13 R145.1 ; port PRXD0
PRXD1: J56.11 R144.1 ; port PRXD1
PRXD2: J56.9 R143.1 ; port PRXD2
PRXD3: J56.7 R142.1 ; port PRXD3
PRXDV: J56.15 R146.1 ; port PRXDV
PRXER: J56.19 R149.1 ; port PRXER
PTXCLK: J56.23 R147.2 R151.2 ; port PTXCLK
PTXD0: J56.27 R153.2 ; port PTXD0
PTXD1: J56.29 R154.2 ; port PTXD1
PTXD2: J56.31 R155.2 ; port PTXD2
PTXD3: J56.33 R156.2 ; port PTXD3
PTXEN: J56.25 R152.2 ; port PTXEN
PTXER: J56.21 R147.1 R150.2 R159.1 R160.1 ; port PTXER
NetC13_1: R139.2 ; port MII_SUP
NetJ58_2: J58.2(MDIO) R140.2
NetJ58_3: J58.3(MDC) R141.2
NetJ58_4: J58.4(RXD3) R142.2
NetJ58_5: J58.5(RXD2) R143.2
NetJ58_6: J58.6(RXD1) R144.2
NetJ58_7: J58.7(RXD0) R145.2
NetJ58_8: J58.8(RX_DV) R146.2
NetJ58_9: J58.9(RX_CLK) R148.2
NetJ58_10: J58.10(RX_ER) R149.2
NetJ58_11: J58.11(TX_ER) R150.1
NetJ58_12: J58.12(TX_CLK) R151.1
NetJ58_13: J58.13(TX_EN) R152.1
NetJ58_14: J58.14(TXD0) R153.1
NetJ58_15: J58.15(TXD1) R154.1
NetJ58_16: J58.16(TXD2) R155.1
NetJ58_17: J58.17(TXD3) R156.1
NetJ58_18: J58.18(COL) R157.2
NetJ58_19: J58.19(CRS) R158.2
NetJ60_23: R160.2 ; port PCLK_OUT

Not connected (* = marked no-connect by the designer): J56 1 39

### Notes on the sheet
- (near R160) Resistor R147, R159 and R160 should be placed close to each other.

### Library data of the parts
C43 C44 = SMALL CAP: Part Description: C/C/ SMD, Tan, 7343; Voltage: 25V; Tolerance: +80-20%
J58 = CON-MII-MALE_0
R139 R147 R150-R156 R159 R160 = R: as R4 on sheet SH B - HP
R140-R146 R148 R149 R157 R158 = R: as R23 on sheet SH C - POWER&CLOCK&MDIO

## Sheet SH J - ALP INTERFACE.SchDoc
size B; Revision: 1.1; SheetNumber: 9; SheetTotal: 10
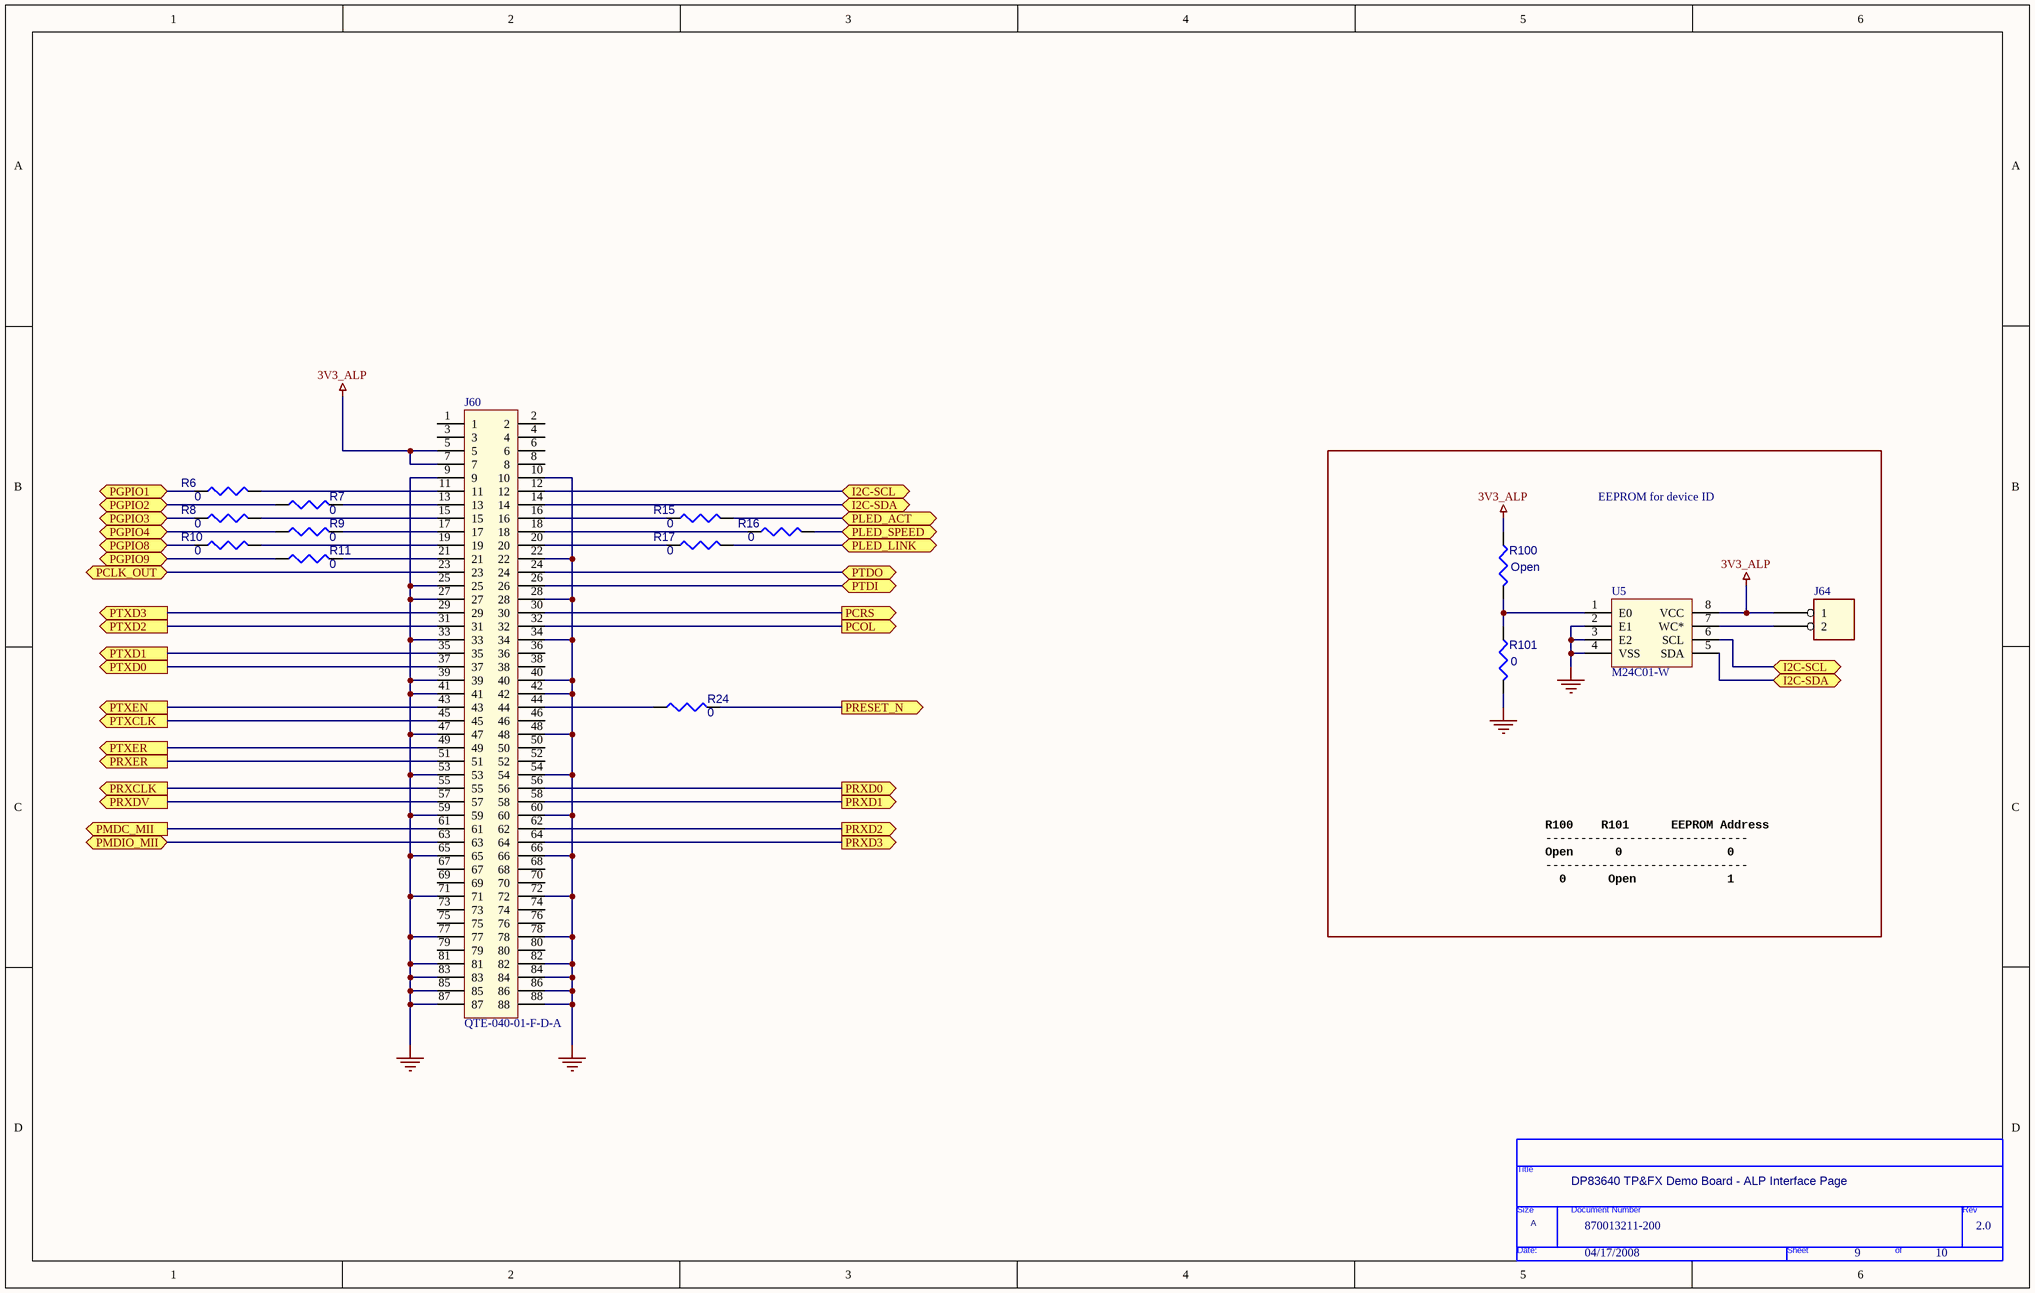
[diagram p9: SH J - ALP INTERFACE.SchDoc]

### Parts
(Parts that share a designator on the sheet are numbered #1, #2 ... from top to bottom, then left to right.)
*#10  Title: DP83640 TP&FX Demo Board - ALP Interface Page  Page Size: A  (hidden comment: TitleBlock0)  (graphical)
J60  QTE-040-01-F-D-A  [QTE-XXX-XX-X-D-XXX-Footprint]
J64  HDR-1X2  [CN-HDR1X2]  (value not drawn)
R6  0  [SMD0603-A-1]
R7  0  [SMD0603-A-1]
R8  0  [SMD0603-A-1]
R9  0  [SMD0603-A-1]
R10  0  [SMD0603-A-1]
R11  0  [SMD0603-A-1]
R15  0  [SMD0603-A-1]
R16  0  [SMD0603-A-1]
R17  0  [SMD0603-A-1]
R24  0  [SMD0603-A-1]
R100  Open  [SMD0603-A-1]
R101  0  [SMD0603-A-1]
U5  M24C01-W  [SO8 (MN)]

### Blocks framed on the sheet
EEPROM for device ID: J64 R100 R101 U5

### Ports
I2C-SCL, I2C-SDA, PCLK_OUT (bidir), PCOL (out), PCRS (out), PGPIO1 (bidir), PGPIO2 (bidir), PGPIO3 (bidir), PGPIO4 (bidir), PGPIO8 (bidir), PGPIO9 (bidir), PLED_ACT (bidir), PLED_LINK (bidir), PLED_SPEED (bidir), PMDC_MII (out), PMDIO_MII (bidir), PRESET_N (out), PRXCLK (out), PRXD0 (out), PRXD1 (out), PRXD2 (out), PRXD3 (out), PRXDV (out), PRXER (out), PTDI (bidir), PTDO (bidir), PTXCLK (out), PTXD0 (out), PTXD1 (out), PTXD2 (out), PTXD3 (out), PTXEN (out), PTXER (out)

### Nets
3V3_ALP: J60.5 J60.7 J64.1 R100.1 U5.8(VCC)
GND: J60.9 J60.10 J60.22 J60.25 J60.27 J60.28 J60.33 J60.34 J60.39 J60.40 J60.41 J60.42 J60.47 J60.48 J60.53 J60.54 J60.59 J60.60 J60.65 J60.66 J60.71 J60.72 J60.77 J60.78 J60.81 J60.82 J60.83 J60.84 J60.85 J60.86 J60.87 J60.88 R101.2 U5.2(E1) U5.3(E2) U5.4(VSS)
PCOL: J60.32 ; port PCOL
PCRS: J60.30 ; port PCRS
PMDC: J60.61 ; port PMDC_MII
PMDIO: J60.63 ; port PMDIO_MII
PRXCLK: J60.55 ; port PRXCLK
PRXD0: J60.56 ; port PRXD0
PRXD1: J60.58 ; port PRXD1
PRXD2: J60.62 ; port PRXD2
PRXD3: J60.64 ; port PRXD3
PRXDV: J60.57 ; port PRXDV
PRXER: J60.51 ; port PRXER
PTXCLK: J60.45 ; port PTXCLK
PTXD0: J60.37 ; port PTXD0
PTXD1: J60.35 ; port PTXD1
PTXD2: J60.31 ; port PTXD2
PTXD3: J60.29 ; port PTXD3
PTXEN: J60.43 ; port PTXEN
PTXER: J60.49 ; port PTXER
NetJ1_1: R6.1 ; port PGPIO1
NetJ1_3: R7.1 ; port PGPIO2
NetJ1_5: R8.1 ; port PGPIO3
NetJ1_7: R9.1 ; port PGPIO4
NetJ1_9: R15.1 ; port PLED_ACT
NetJ1_11: R16.1 ; port PLED_SPEED
NetJ1_13: R17.1 ; port PLED_LINK
NetJ1_15: R10.1 ; port PGPIO8
NetJ1_17: R11.1 ; port PGPIO9
NetJ8_1: R24.2 ; port PRESET_N
NetJ60_11: J60.11 R6.2
NetJ60_12: J60.12 U5.6(SCL) ; port I2C-SCL
NetJ60_13: J60.13 R7.2
NetJ60_14: J60.14 U5.5(SDA) ; port I2C-SDA
NetJ60_15: J60.15 R8.2
NetJ60_16: J60.16 R15.2
NetJ60_17: J60.17 R9.2
NetJ60_18: J60.18 R16.2
NetJ60_19: J60.19 R10.2
NetJ60_20: J60.20 R17.2
NetJ60_21: J60.21 R11.2
NetJ60_23: J60.23 ; port PCLK_OUT
NetJ60_24: J60.24 ; port PTDO
NetJ60_26: J60.26 ; port PTDI
NetJ60_44: J60.44 R24.1
NetJ64_2: J64.2 U5.7(WC*)
NetR100_2: R100.2 R101.1 U5.1(E0)

Not connected (* = marked no-connect by the designer): J60 1 2 3 4 6 8 36 38 46 50 52 67 68 69 70 73 74 75 76 79 80

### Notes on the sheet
- R100    R101      EEPROM Address
  -----------------------------  Open      0               0
  -----------------------------
  0      Open             1

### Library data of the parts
R6-R11 R15-R17 R24 = R: as R4 on sheet SH B - HP
R100 R101 = R: as R1 on sheet SH B - HP

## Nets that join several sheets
3V3: SH B - HP (6 pins), SH C - POWER&CLOCK&MDIO (6 pins), SH E - STRAP OPTIONS (6 pins), SH F - GPIO (16 pins), SH G - TP Integrated Magnetics (R99.1)
3V3_ALP: SH C - POWER&CLOCK&MDIO (J12.1), SH J - ALP INTERFACE (5 pins)
3V3_USB: SH K - USB Interface (20 pins), SH C - POWER&CLOCK&MDIO (J12.3)
GND: SH K - USB Interface (26 pins), SH B - HP (37 pins), SH C - POWER&CLOCK&MDIO (13 pins), SH E - STRAP OPTIONS (J24.2 J25.2 R46.2), SH F - GPIO (21 pins), SH G - TP Integrated Magnetics (9 pins), SH H - zFX (15 pins), SH I - MII (40 pins), SH J - ALP INTERFACE (36 pins)
VCT: SH G - TP Integrated Magnetics (11 pins), SH H - zFX (13 pins)
NetC13_1: SH C - POWER&CLOCK&MDIO (C13.1 J55.1 R28.1 U2.2), SH I - MII (R139.2)
NetJ1_1: SH K - USB Interface (R38.2), SH B - HP (J1.1 U1.21), SH F - GPIO (J32.2), SH J - ALP INTERFACE (R6.1)
NetJ1_3: SH K - USB Interface (R39.2), SH B - HP (J1.3 U1.22), SH F - GPIO (J35.2), SH J - ALP INTERFACE (R7.1)
NetJ1_5: SH K - USB Interface (R40.2), SH B - HP (J1.5 U1.23), SH F - GPIO (J38.2), SH J - ALP INTERFACE (R8.1)
NetJ1_7: SH K - USB Interface (R41.2), SH B - HP (J1.7 U1.25), SH F - GPIO (J41.2), SH J - ALP INTERFACE (R9.1)
NetJ1_9: SH K - USB Interface (R161.1), SH B - HP (J1.9 U1.26), SH F - GPIO (J33.2), SH J - ALP INTERFACE (R15.1)
NetJ1_11: SH K - USB Interface (R74.1), SH B - HP (J1.11 R162.2), SH F - GPIO (J36.2), SH J - ALP INTERFACE (R16.1)
NetJ1_13: SH K - USB Interface (R71.1), SH B - HP (J1.13 U1.28), SH F - GPIO (J39.2), SH J - ALP INTERFACE (R17.1)
NetJ1_15: SH K - USB Interface (R53.2), SH B - HP (J1.15 R31.1 U1.36), SH F - GPIO (J42.2), SH J - ALP INTERFACE (R10.1)
NetJ1_17: SH K - USB Interface (R56.2), SH B - HP (J1.17 U1.37), SH F - GPIO (R86.1), SH J - ALP INTERFACE (R11.1)
NetJ1_23: SH K - USB Interface (R59.1), SH B - HP (J1.23 R1.1 R18.1 U1.24)
NetJ3_2: SH B - HP (R5.1), SH C - POWER&CLOCK&MDIO (J3.2)
NetJ3_3: SH K - USB Interface (R37.2), SH C - POWER&CLOCK&MDIO (J3.3)
NetJ4_2: SH B - HP (R4.1), SH C - POWER&CLOCK&MDIO (J4.2)
NetJ4_3: SH K - USB Interface (R36.2), SH C - POWER&CLOCK&MDIO (J4.3)
NetJ8_1: SH K - USB Interface (R89.1), SH B - HP (J8.1 R31.2 R92.1 U1.29), SH J - ALP INTERFACE (R24.2)
NetJ60_23: SH B - HP (R18.2), SH I - MII (R160.2), SH J - ALP INTERFACE (J60.23)
NetJ60_24: SH B - HP (R13.2), SH J - ALP INTERFACE (J60.24)
NetJ60_26: SH B - HP (R14.2), SH J - ALP INTERFACE (J60.26)
NetR22_1: SH B - HP (U1.33), SH C - POWER&CLOCK&MDIO (R22.1)
NetR25_1: SH B - HP (U1.34), SH C - POWER&CLOCK&MDIO (R25.1 R27.2)
NetR112_1: SH B - HP (U1.17), SH G - TP Integrated Magnetics (R112.1), SH H - zFX (R113.2)
NetR114_2: SH B - HP (U1.16), SH G - TP Integrated Magnetics (R115.2), SH H - zFX (R114.2)
NetR116_2: SH B - HP (U1.13), SH G - TP Integrated Magnetics (R116.2), SH H - zFX (R117.2)
NetR118_2: SH B - HP (U1.14), SH G - TP Integrated Magnetics (R119.1), SH H - zFX (R118.2)
NetR128_1: SH B - HP (R162.1 U1.27), SH H - zFX (R128.1)
PCOL: SH B - HP (U1.42), SH E - STRAP OPTIONS (R43.1), SH I - MII (J56.35 R157.1), SH J - ALP INTERFACE (J60.32)
PCRS: SH B - HP (U1.40), SH E - STRAP OPTIONS (R44.1), SH I - MII (J56.37 R158.1), SH J - ALP INTERFACE (J60.30)
PMDC: SH C - POWER&CLOCK&MDIO (J3.1), SH I - MII (J56.5 R141.1), SH J - ALP INTERFACE (J60.61)
PMDIO: SH C - POWER&CLOCK&MDIO (J4.1), SH I - MII (J56.3 R140.1), SH J - ALP INTERFACE (J60.63)
PRXCLK: SH B - HP (U1.38), SH I - MII (J56.17 R148.1 R159.2), SH J - ALP INTERFACE (J60.55)
PRXD0: SH B - HP (U1.46), SH E - STRAP OPTIONS (R50.1), SH I - MII (J56.13 R145.1), SH J - ALP INTERFACE (J60.56)
PRXD1: SH B - HP (U1.45), SH E - STRAP OPTIONS (R49.1), SH I - MII (J56.11 R144.1), SH J - ALP INTERFACE (J60.58)
PRXD2: SH B - HP (U1.44), SH E - STRAP OPTIONS (R47.1), SH I - MII (J56.9 R143.1), SH J - ALP INTERFACE (J60.62)
PRXD3: SH B - HP (U1.43), SH E - STRAP OPTIONS (R45.1), SH I - MII (J56.7 R142.1), SH J - ALP INTERFACE (J60.64)
PRXDV: SH B - HP (U1.39), SH E - STRAP OPTIONS (R42.1), SH I - MII (J56.15 R146.1), SH J - ALP INTERFACE (J60.57)
PRXER: SH B - HP (U1.41), SH E - STRAP OPTIONS (R46.1), SH I - MII (J56.19 R149.1), SH J - ALP INTERFACE (J60.51)
PTXCLK: SH B - HP (U1.1), SH I - MII (J56.23 R147.2 R151.2), SH J - ALP INTERFACE (J60.45)
PTXD0: SH B - HP (U1.3), SH I - MII (J56.27 R153.2), SH J - ALP INTERFACE (J60.37)
PTXD1: SH B - HP (U1.4), SH I - MII (J56.29 R154.2), SH J - ALP INTERFACE (J60.35)
PTXD2: SH B - HP (U1.5), SH I - MII (J56.31 R155.2), SH J - ALP INTERFACE (J60.31)
PTXD3: SH B - HP (U1.6), SH E - STRAP OPTIONS (R48.1), SH I - MII (J56.33 R156.2), SH J - ALP INTERFACE (J60.29)
PTXEN: SH B - HP (U1.2), SH I - MII (J56.25 R152.2), SH J - ALP INTERFACE (J60.43)
PTXER: SH I - MII (5 pins), SH J - ALP INTERFACE (J60.49)
TDI: SH K - USB Interface (R65.1), SH B - HP (J1.21 R14.1 R164.1 U1.12)
TDO: SH K - USB Interface (R68.1), SH B - HP (J1.19 R13.1 R163.1 U1.9)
